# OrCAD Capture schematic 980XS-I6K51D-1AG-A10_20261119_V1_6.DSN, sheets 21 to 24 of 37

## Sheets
21 T01.GROUP1.U2: size D
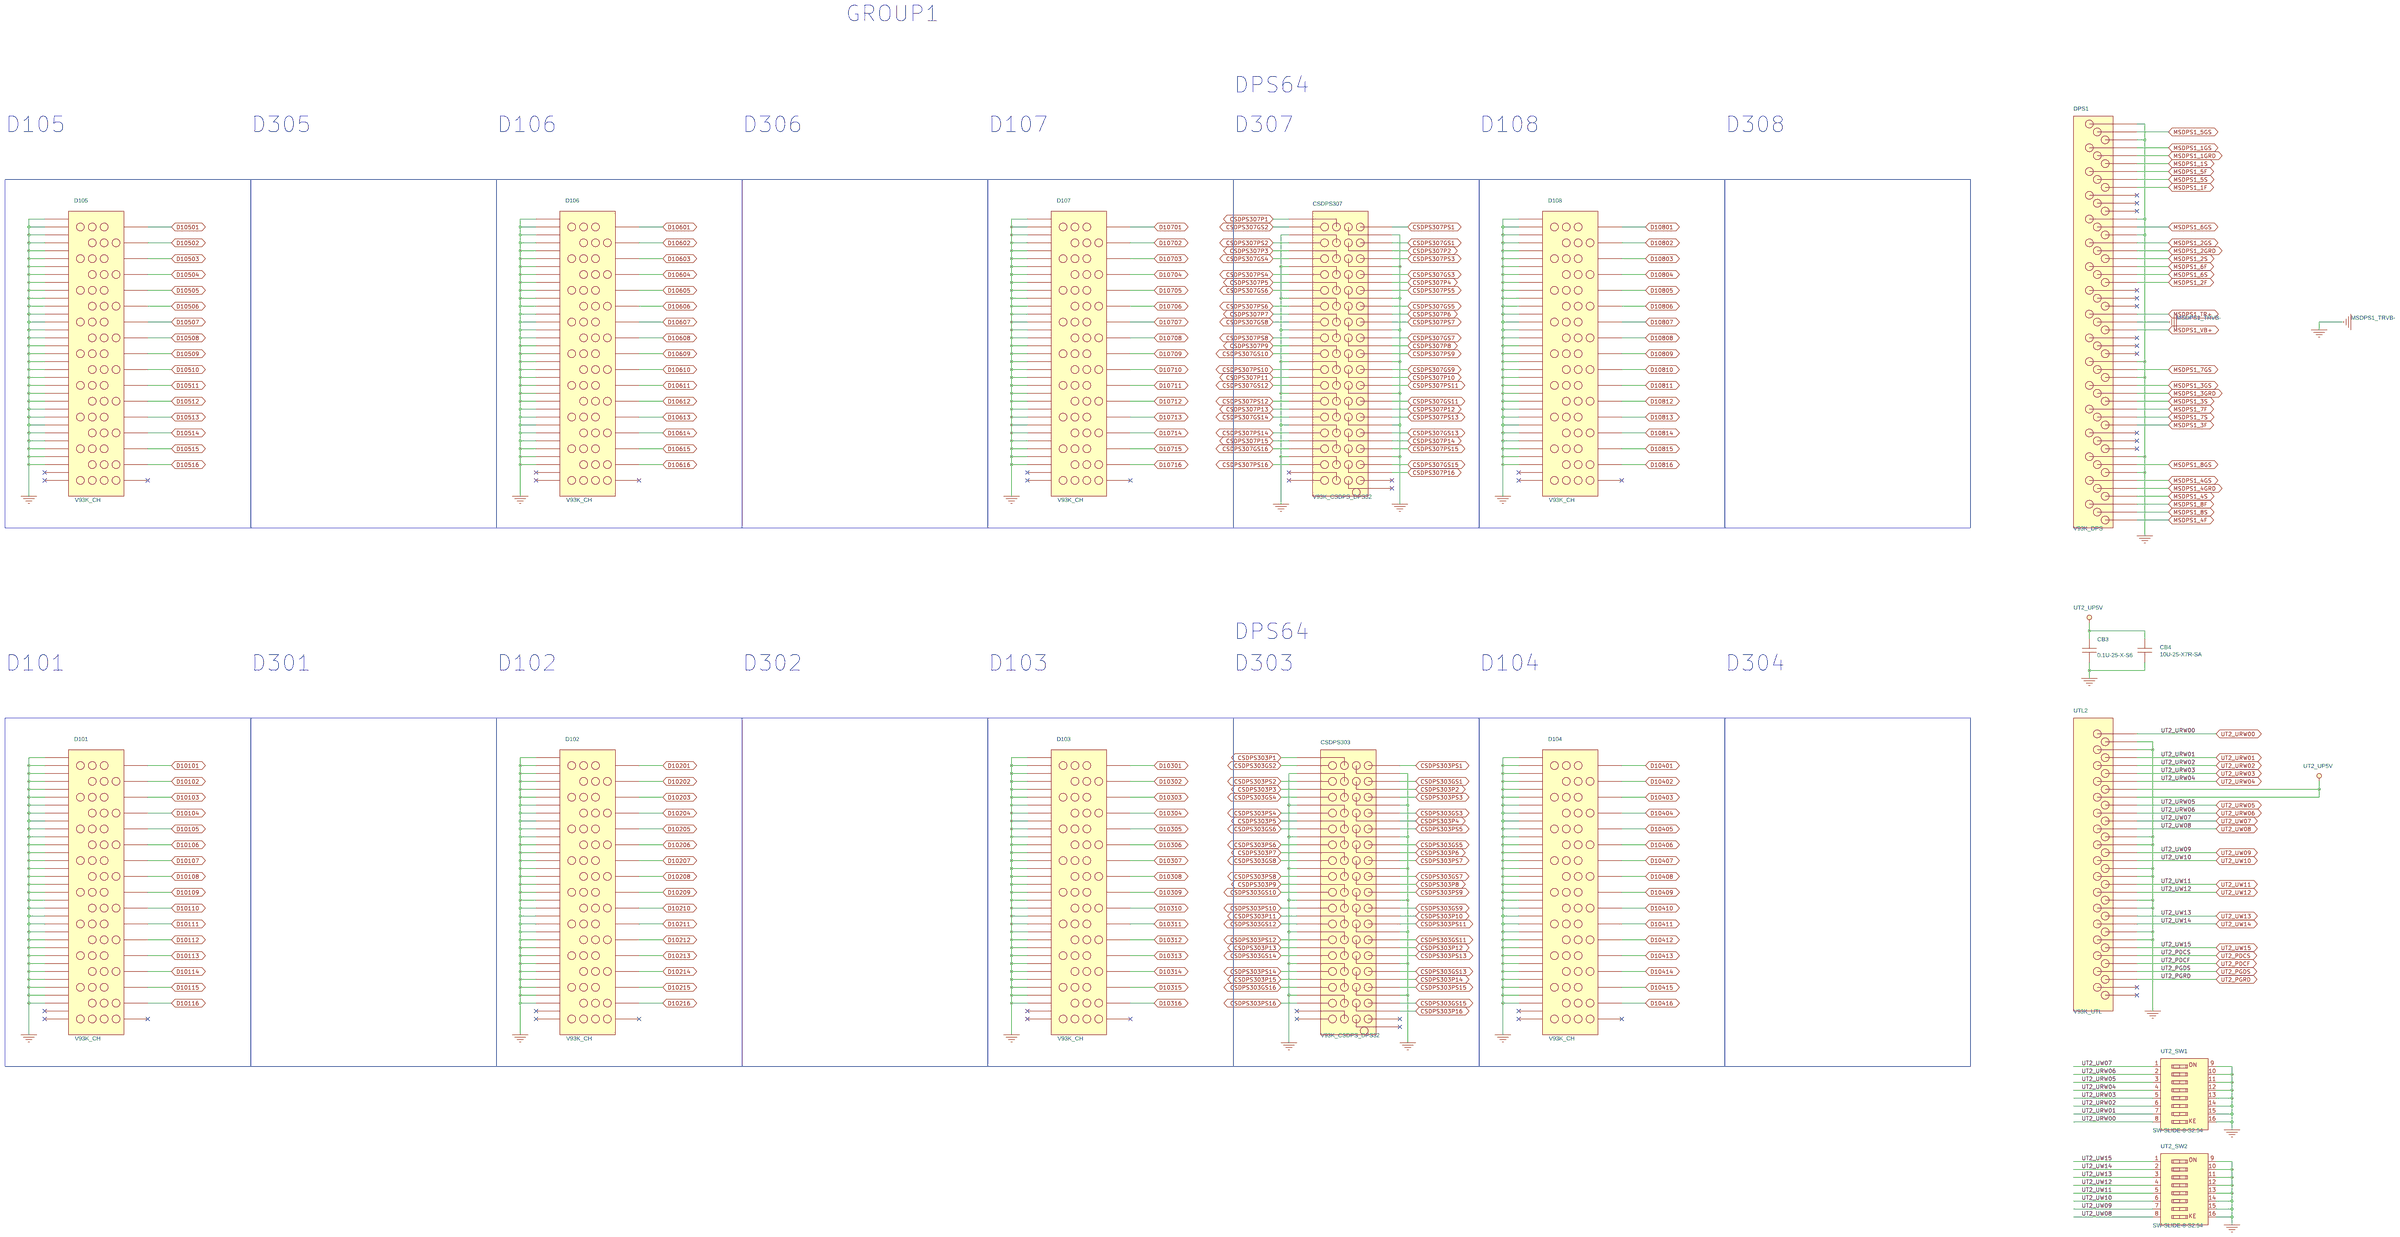
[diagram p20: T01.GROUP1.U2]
22 T02.GROUP2.U3: size D
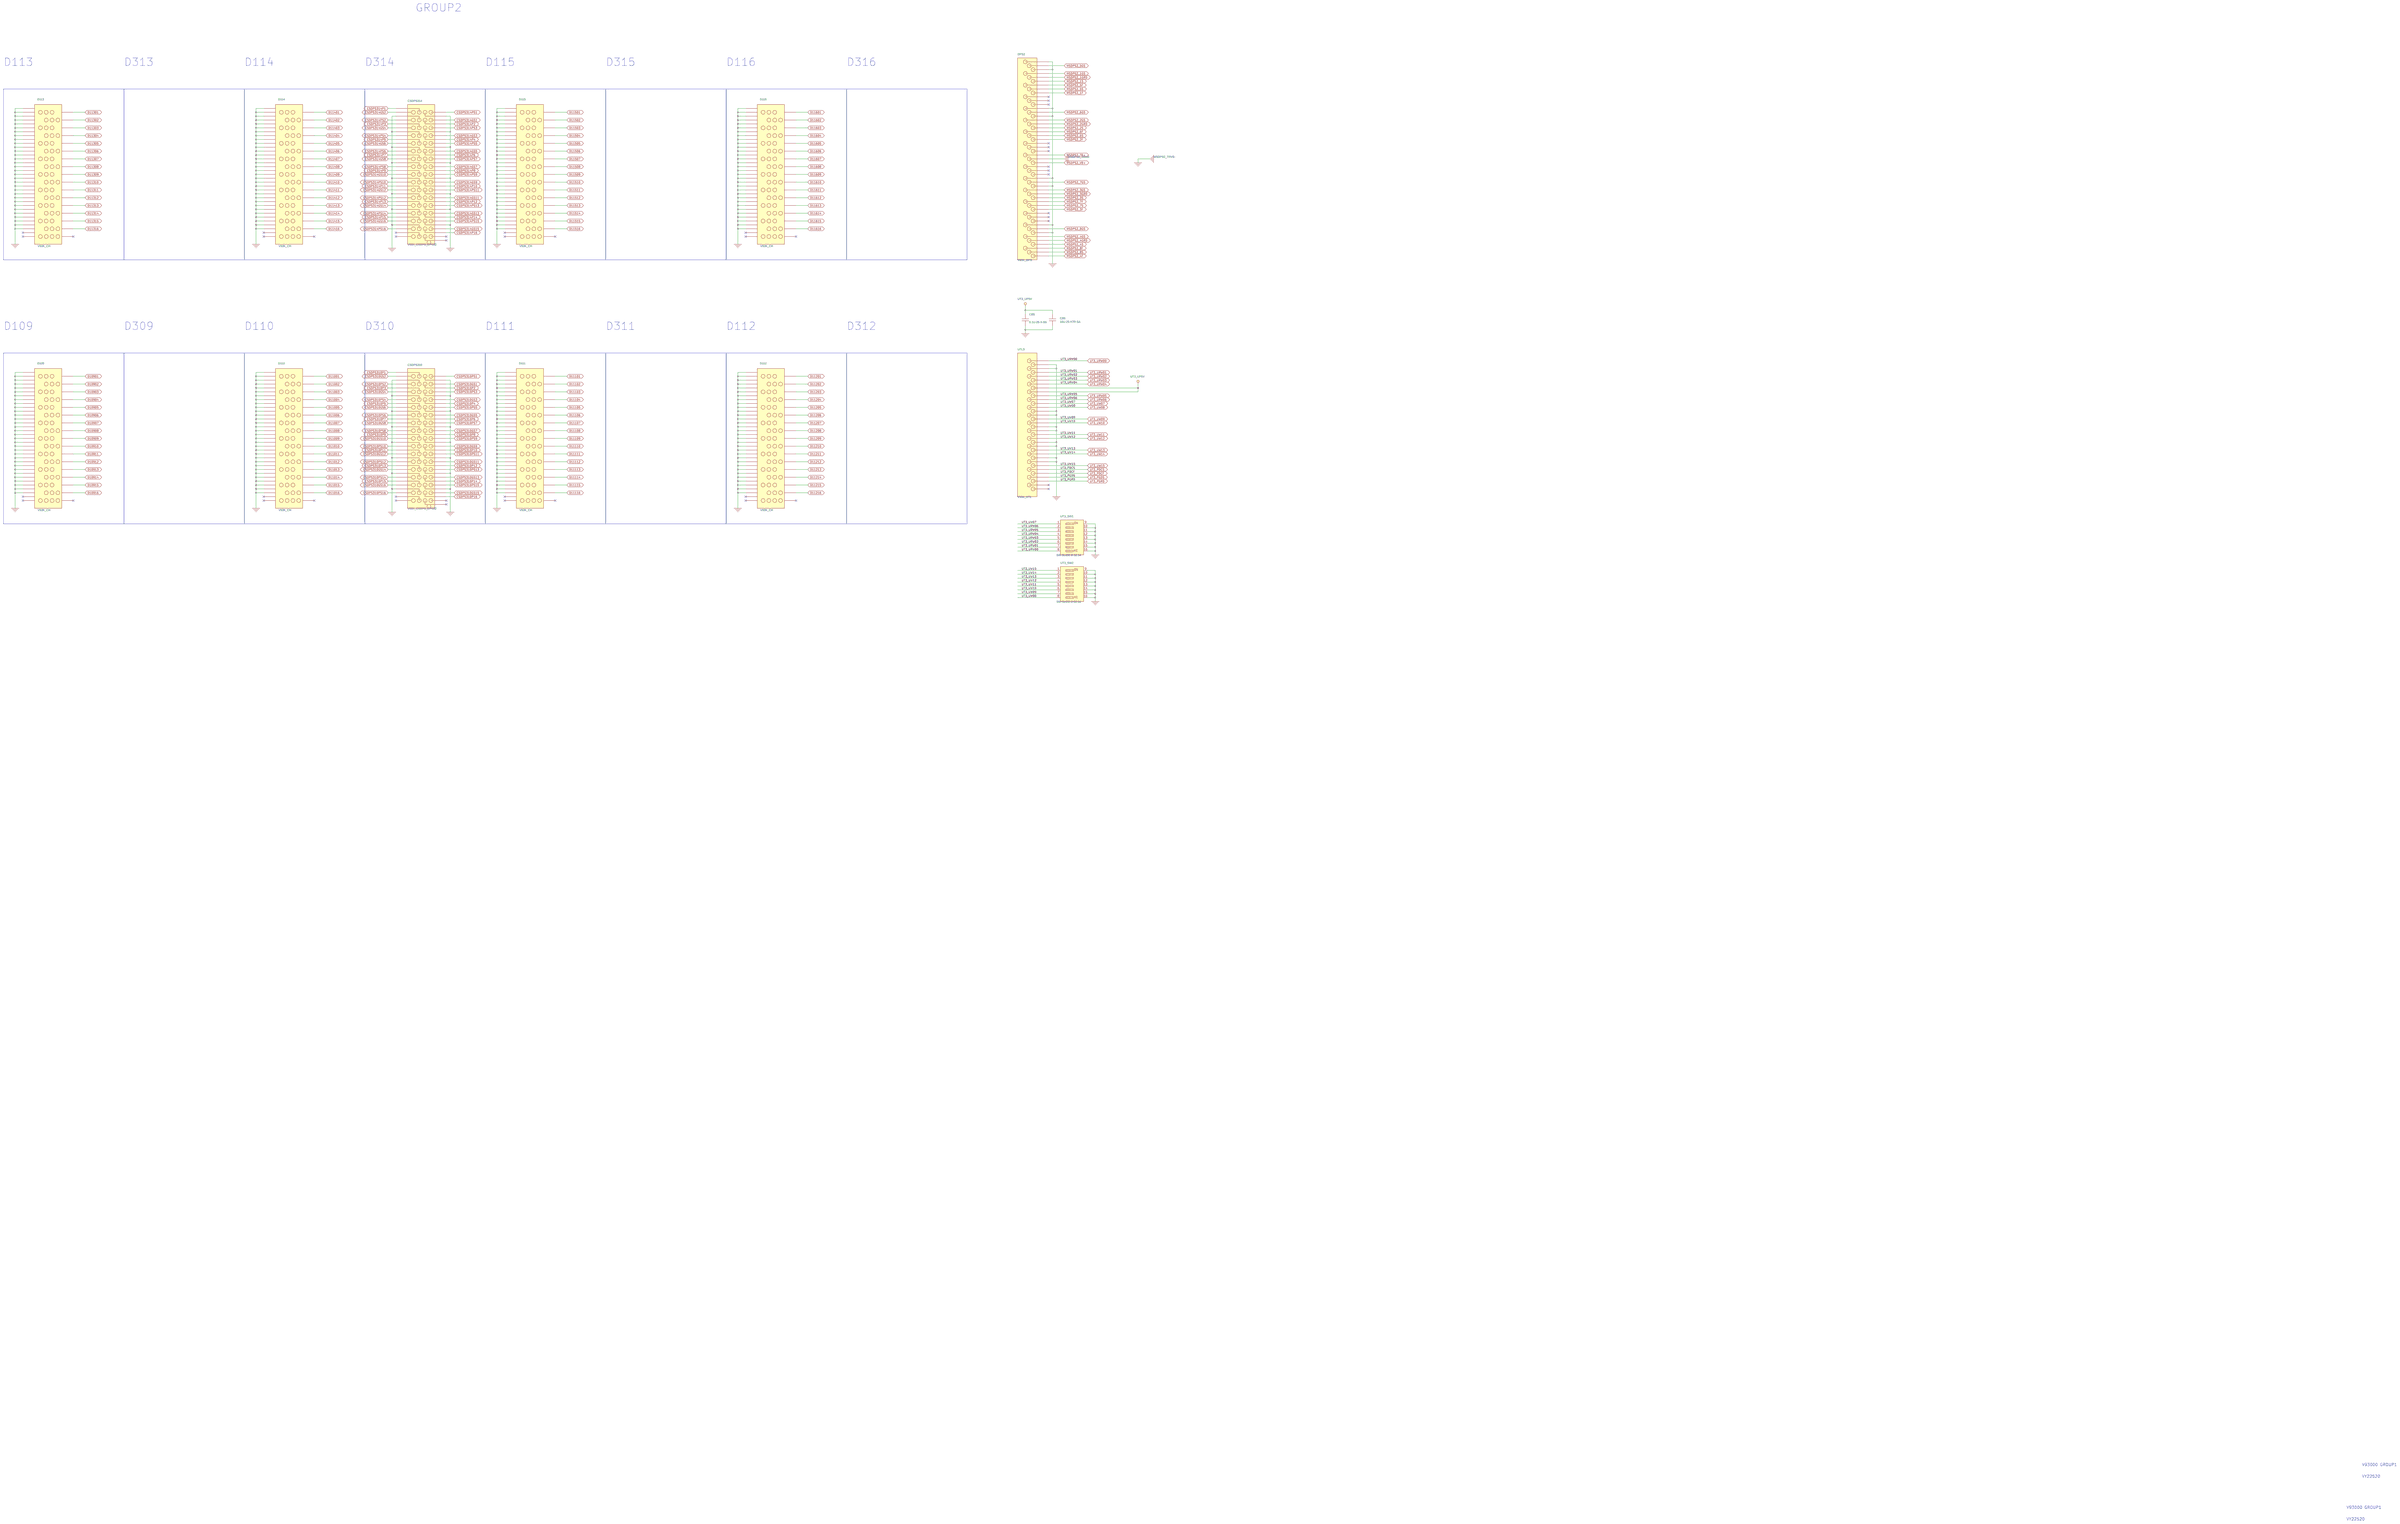
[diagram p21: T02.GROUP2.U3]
23 T03.GROUP3.U1: size D
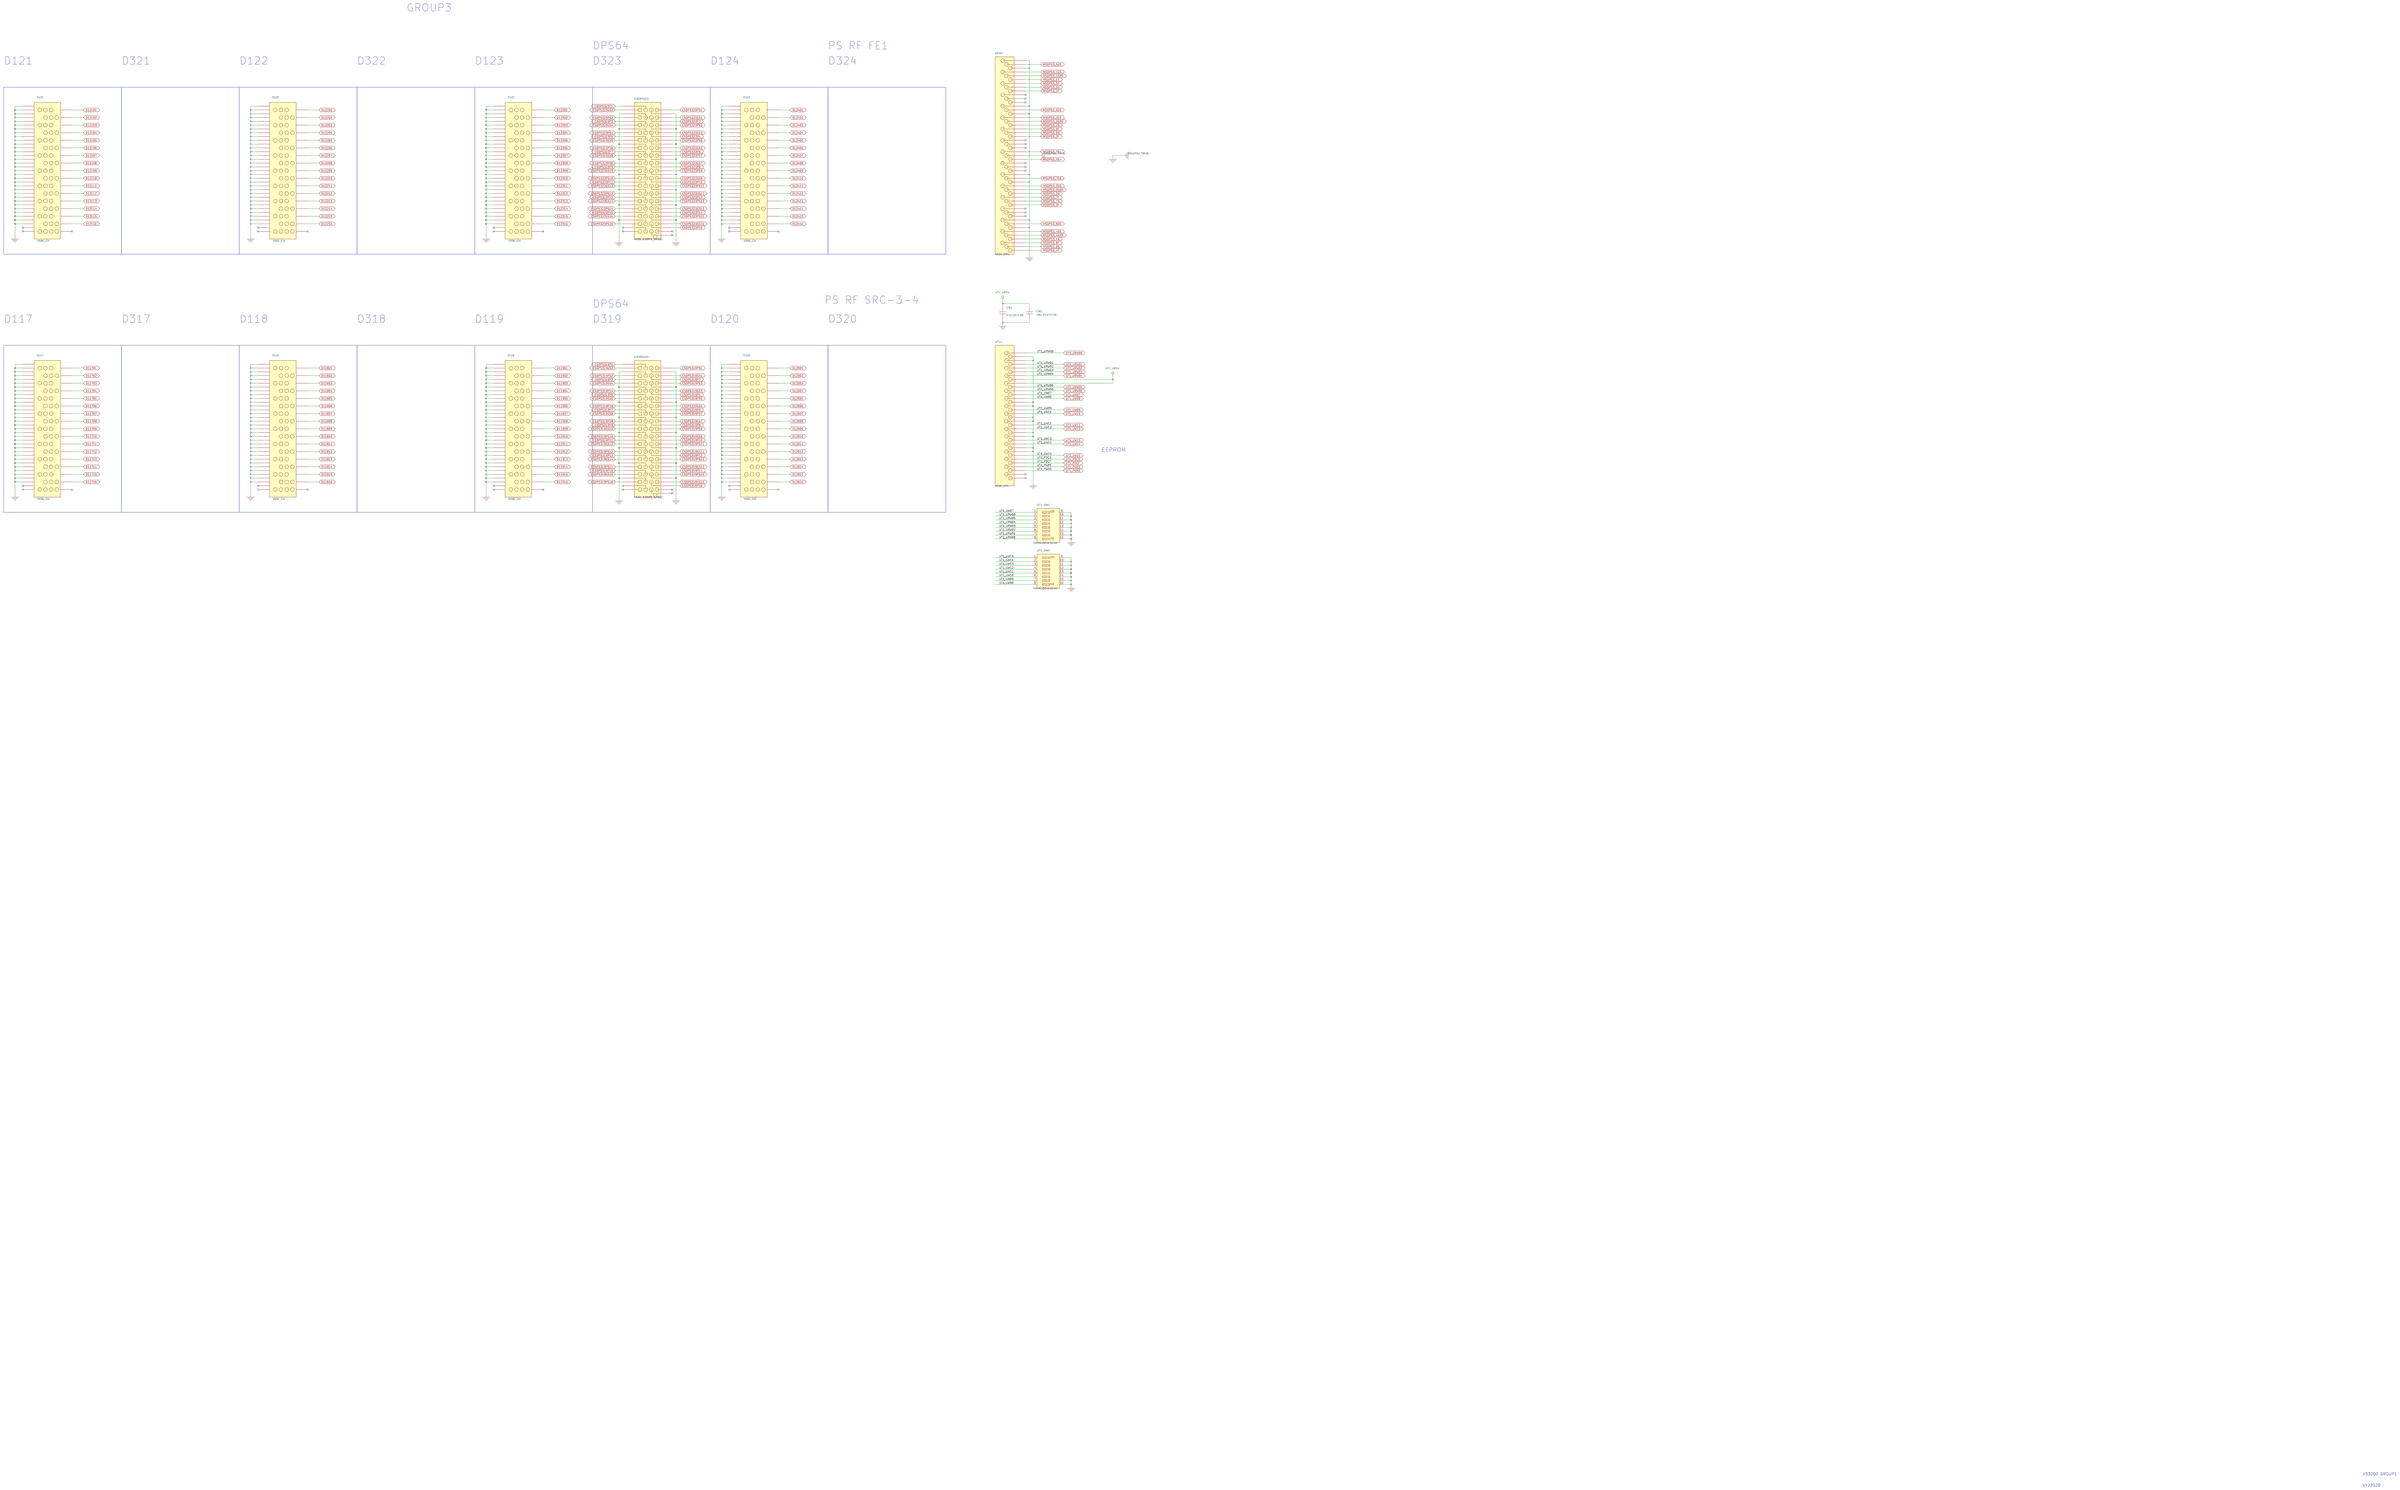
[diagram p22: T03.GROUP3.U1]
24 T04.GROUP8.U4: size D
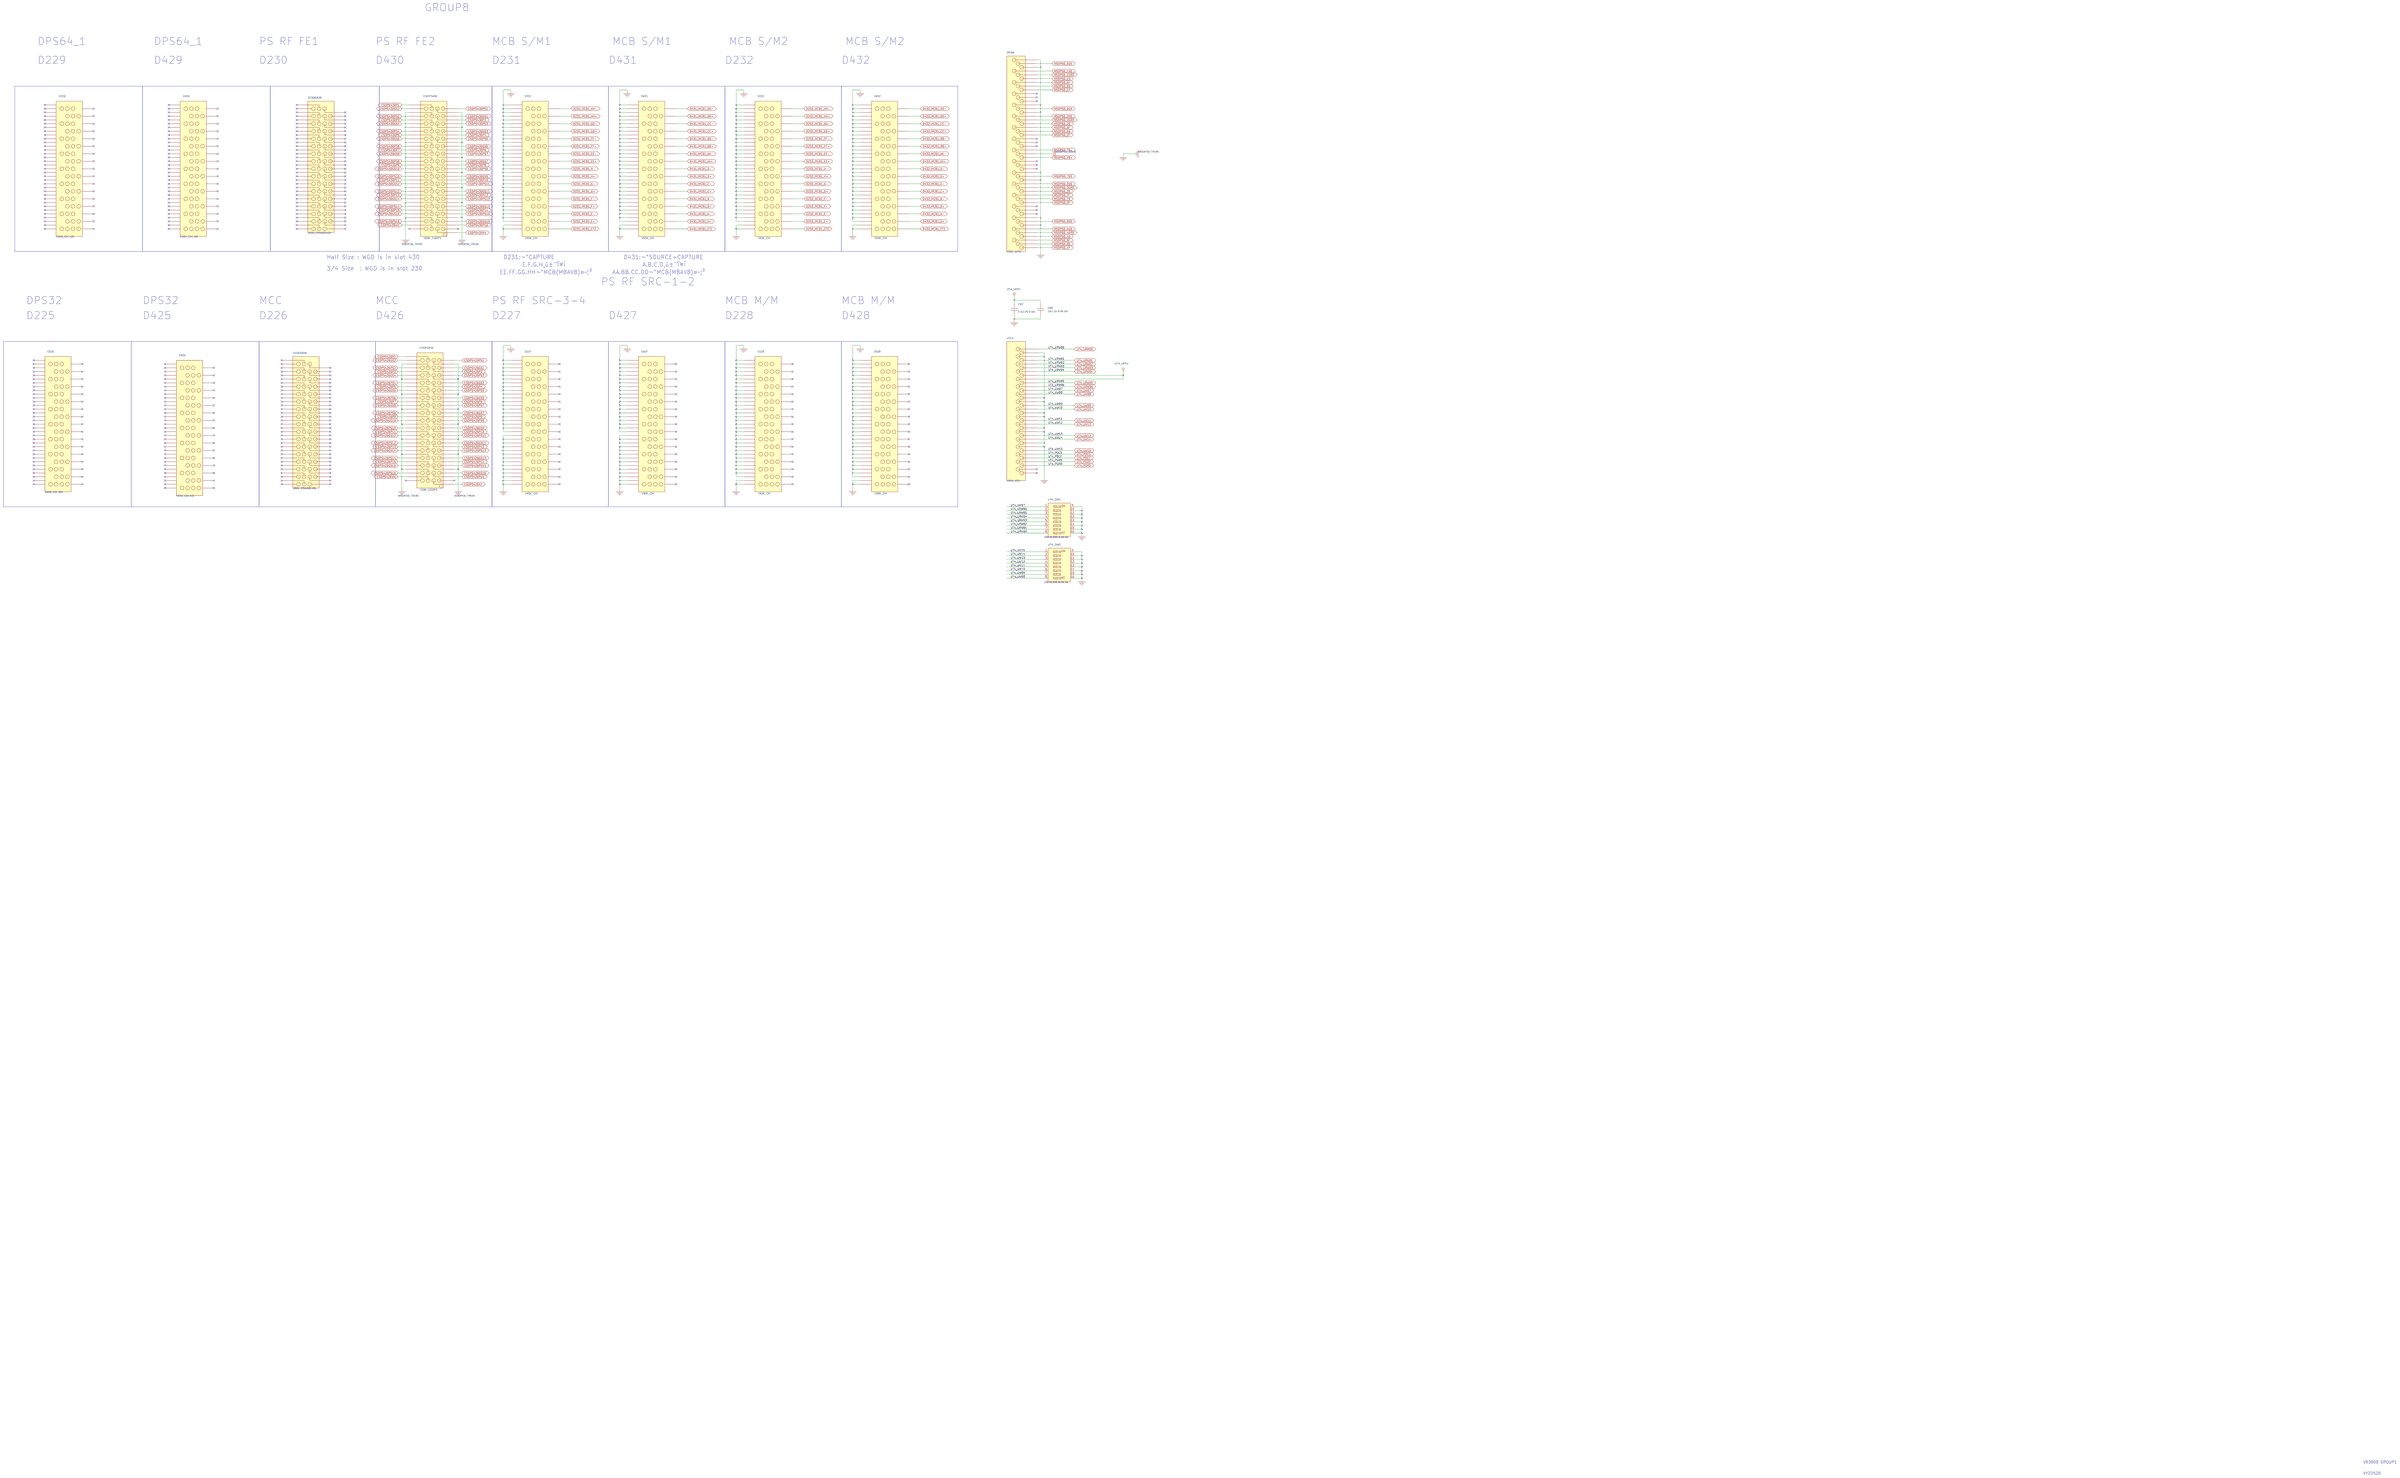
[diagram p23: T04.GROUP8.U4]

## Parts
sheet T01.GROUP1.U2
CB3  0.1U-25-X-S6  [C0603]
CB4  10U-25-X7R-SA  [C1206]
CSDPS303  V93K_CSDPS_DPS32  [PG_VG93K_PF_DPS32_G1D303]
CSDPS307  V93K_CSDPS_DPS32  [PG_VG93K_PF_DPS32_G1D307]
D101  V93K_CH  [PG_VG93K_F_G1D101]
D102  V93K_CH  [PG_VG93K_F_G1D102]
D103  V93K_CH  [PG_VG93K_F_G1D103]
D104  V93K_CH  [PG_VG93K_F_G1D104]
D105  V93K_CH  [PG_VG93K_F_G1D105]
D106  V93K_CH  [PG_VG93K_F_G1D106]
D107  V93K_CH  [PG_VG93K_F_G1D107]
D108  V93K_CH  [PG_VG93K_F_G1D108]
DPS1  V93K_DPS  [PG_VG93K_F_G1DPS1]
UT2_SW1  SW-SLIDE-8-S2.54  [SW8X2_2P54MM_16P_SMD]
UT2_SW2  SW-SLIDE-8-S2.54  [SW8X2_2P54MM_16P_SMD]
UTL2  V93K_UTL  [PG_VG93K_F_G1UTI2]
sheet T02.GROUP2.U3
CB5  0.1U-25-X-S6  [C0603]
CB6  10U-25-X7R-SA  [C1206]
CSDPS310  V93K_CSDPS_DPS32  [PG_VG93K_PF_DPS32_G2D310]
CSDPS314  V93K_CSDPS_DPS32  [PG_VG93K_PF_DPS32_G2D314]
D109  V93K_CH  [PG_VG93K_F_G2D109]
D110  V93K_CH  [PG_VG93K_F_G2D110]
D111  V93K_CH  [PG_VG93K_F_G2D111]
D112  V93K_CH  [PG_VG93K_F_G2D112]
D113  V93K_CH  [PG_VG93K_F_G2D113]
D114  V93K_CH  [PG_VG93K_F_G2D114]
D115  V93K_CH  [PG_VG93K_F_G2D115]
D116  V93K_CH  [PG_VG93K_F_G2D116]
DPS2  V93K_DPS  [PG_VG93K_F_G2DPS2]
UT3_SW1  SW-SLIDE-8-S2.54  [SW8X2_2P54MM_16P_SMD]
UT3_SW2  SW-SLIDE-8-S2.54  [SW8X2_2P54MM_16P_SMD]
UTL3  V93K_UTL  [PG_VG93K_F_G2UTI3]
sheet T03.GROUP3.U1
CB1  0.1U-25-X-S6  [C0603]
CB2  10U-25-X7R-SA  [C1206]
CSDPS319  V93K_CSDPS_DPS32  [PG_VG93K_PF_DPS32_G3D319]
CSDPS323  V93K_CSDPS_DPS32  [PG_VG93K_PF_DPS32_G3D323]
D117  V93K_CH  [PG_VG93K_F_G3D117]
D118  V93K_CH  [PG_VG93K_F_G3D118]
D119  V93K_CH  [PG_VG93K_F_G3D119]
D120  V93K_CH  [PG_VG93K_F_G3D120]
D121  V93K_CH  [PG_VG93K_F_G3D121]
D122  V93K_CH  [PG_VG93K_F_G3D122]
D123  V93K_CH  [PG_VG93K_F_G3D123]
D124  V93K_CH  [PG_VG93K_F_G3D124]
DPS3  V93K_DPS  [PG_VG93K_F_G3DPS3]
UT1_SW1  SW-SLIDE-8-S2.54  [SW8X2_2P54MM_16P_SMD]
UT1_SW2  SW-SLIDE-8-S2.54  [SW8X2_2P54MM_16P_SMD]
UTL1  V93K_UTL  [PG_VG93K_F_G3UTI1]
sheet T04.GROUP8.U4
CB7  0.1U-25-X-S6  [C0603]
CB8  10U-25-X7R-SA  [C1206]
CSDPS426  V93K_CSDPS  [PG_VG93K_PF_DPS32_G8D426]
CSDPS430  V93K_CSDPS  [PG_VG93K_PF_DPS32_G8D430]
D225  V93K_CH_ND  [PG_VG93K_F_G8D225_ND]
D226/D626  V93K_PS1600 HD  [PG_VG93K_F_HSM_G8D226_626_ND]
D227  V93K_CH  [PG_VG93K_F_G8D227]
D228  V93K_CH  [PG_VG93K_F_G8D228]
D229  V93K_CH_ND  [PG_VG93K_F_G8D229_ND]
D230/D630  V93K_PS1600 HD  [PG_VG93K_F_HSM_G8D230_630_ND]
D231  V93K_CH  [PG_VG93K_F_G8D231]
D232  V93K_CH  [PG_VG93K_F_G8D232]
D425  V93K_CH_ND  [PG_VG93K_F_G8D425_ND]
D427  V93K_CH  [PG_VG93K_F_G8D427]
D428  V93K_CH  [PG_VG93K_F_G8D428]
D429  V93K_CH_ND  [PG_VG93K_F_G8D429_ND]
D431  V93K_CH  [PG_VG93K_F_G8D431]
D432  V93K_CH  [PG_VG93K_F_G8D432]
DPS8  V93K_DPS  [PG_VG93K_F_G8DPS8]
UT4_SW1  SW-SLIDE-8-S2.54  [SW8X2_2P54MM_16P_SMD]
UT4_SW2  SW-SLIDE-8-S2.54  [SW8X2_2P54MM_16P_SMD]
UTL4  V93K_UTL  [PG_VG93K_F_G8UTI4]

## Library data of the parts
CB1 CB3 CB5 CB7 = 0.1U-25-X-S6
CB2 CB4 CB6 CB8 = 10U-25-X7R-SA
CSDPS303 CSDPS307 CSDPS310 CSDPS314 CSDPS319 CSDPS323 = V93K_CSDPS_DPS32
D101-D124 D225 D227-D229 D231 D232 D425 D427-D429 D431 D432 = V93K_CH
DPS1-DPS3 DPS8 = V93K_DPS
UT1_SW1 UT1_SW2 UT2_SW1 UT2_SW2 UT3_SW1 UT3_SW2 UT4_SW1 UT4_SW2 = SW-SLIDE-8-S2.54
UTL1-UTL4 = V93K_UTL
CSDPS426 CSDPS430 = V93K_CSDPS_A
D226/D626 D230/D630 = V93K_PS1600_HD

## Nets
DGND: CSDPS303.B2 CSDPS303.B4 CSDPS303.B6 CSDPS303.B8 CSDPS303.B10 CSDPS303.B12 CSDPS303.B14 CSDPS303.B16 CSDPS303.C1 CSDPS303.C3 CSDPS303.C5 CSDPS303.C7 CSDPS303.C9 CSDPS303.C11 CSDPS303.C13 CSDPS303.C15 CSDPS307.B2 CSDPS307.B4 CSDPS307.B6 CSDPS307.B8 CSDPS307.B10 CSDPS307.B12 CSDPS307.B14 CSDPS307.B16 CSDPS307.C1 CSDPS307.C3 CSDPS307.C5 CSDPS307.C7 CSDPS307.C9 CSDPS307.C11 CSDPS307.C13 CSDPS307.C15 CSDPS310.B2 CSDPS310.B4 CSDPS310.B6 CSDPS310.B8 CSDPS310.B10 CSDPS310.B12 CSDPS310.B14 CSDPS310.B16 CSDPS310.C1 CSDPS310.C3 CSDPS310.C5 CSDPS310.C7 CSDPS310.C9 CSDPS310.C11 CSDPS310.C13 CSDPS310.C15 CSDPS314.B2 CSDPS314.B4 CSDPS314.B6 CSDPS314.B8 CSDPS314.B10 CSDPS314.B12 CSDPS314.B14 CSDPS314.B16 CSDPS314.C1 CSDPS314.C3 CSDPS314.C5 CSDPS314.C7 CSDPS314.C9 CSDPS314.C11 CSDPS314.C13 CSDPS314.C15 CSDPS319.B2 CSDPS319.B4 CSDPS319.B6 CSDPS319.B8 CSDPS319.B10 CSDPS319.B12 CSDPS319.B14 CSDPS319.B16 CSDPS319.C1 CSDPS319.C3 CSDPS319.C5 CSDPS319.C7 CSDPS319.C9 CSDPS319.C11 CSDPS319.C13 CSDPS319.C15 CSDPS323.B2 CSDPS323.B4 CSDPS323.B6 CSDPS323.B8 CSDPS323.B10 CSDPS323.B12 CSDPS323.B14 CSDPS323.B16 CSDPS323.C1 CSDPS323.C3 CSDPS323.C5 CSDPS323.C7 CSDPS323.C9 CSDPS323.C11 CSDPS323.C13 CSDPS323.C15 CSDPS426.B2 CSDPS426.B4 CSDPS426.B6 CSDPS426.B8 CSDPS426.B10 CSDPS426.B12 CSDPS426.B14 CSDPS426.B16 CSDPS426.C1 CSDPS426.C3 CSDPS426.C5 CSDPS426.C7 CSDPS426.C9 CSDPS426.C11 CSDPS426.C13 CSDPS426.C15 CSDPS430.B2 CSDPS430.B4 CSDPS430.B6 CSDPS430.B8 CSDPS430.B10 CSDPS430.B12 CSDPS430.B14 CSDPS430.B16 CSDPS430.C1 CSDPS430.C3 CSDPS430.C5 CSDPS430.C7 CSDPS430.C9 CSDPS430.C11 CSDPS430.C13 CSDPS430.C15 D101.A1 D101.A2 D101.A3 D101.A4 D101.A5 D101.A6 D101.A7 D101.A8 D101.A9 D101.A10 D101.A11 D101.A12 D101.A13 D101.A14 D101.A15 D101.A16 D101.B1 D101.B2 D101.B3 D101.B4 D101.B5 D101.B6 D101.B7 D101.B8 D101.B9 D101.B10 D101.B11 D101.B12 D101.B13 D101.B14 D101.B15 D101.B16 D102.A1 D102.A2 D102.A3 D102.A4 D102.A5 D102.A6 D102.A7 D102.A8 D102.A9 D102.A10 D102.A11 D102.A12 D102.A13 D102.A14 D102.A15 D102.A16 D102.B1 D102.B2 D102.B3 D102.B4 D102.B5 D102.B6 D102.B7 D102.B8 D102.B9 D102.B10 D102.B11 D102.B12 D102.B13 D102.B14 D102.B15 D102.B16 D103.A1 D103.A2 D103.A3 D103.A4 D103.A5 D103.A6 D103.A7 D103.A8 D103.A9 D103.A10 D103.A11 D103.A12 D103.A13 D103.A14 D103.A15 D103.A16 D103.B1 D103.B2 D103.B3 D103.B4 D103.B5 D103.B6 D103.B7 D103.B8 D103.B9 D103.B10 D103.B11 D103.B12 D103.B13 D103.B14 D103.B15 D103.B16 D104.A1 D104.A2 D104.A3 D104.A4 D104.A5 D104.A6 D104.A7 D104.A8 D104.A9 D104.A10 D104.A11 D104.A12 D104.A13 D104.A14 D104.A15 D104.A16 D104.B1 D104.B2 D104.B3 D104.B4 D104.B5 D104.B6 D104.B7 D104.B8 D104.B9 D104.B10 D104.B11 D104.B12 D104.B13 D104.B14 D104.B15 D104.B16 D105.A1 D105.A2 D105.A3 D105.A4 D105.A5 D105.A6 D105.A7 D105.A8 D105.A9 D105.A10 D105.A11 D105.A12 D105.A13 D105.A14 D105.A15 D105.A16 D105.B1 D105.B2 D105.B3 D105.B4 D105.B5 D105.B6 D105.B7 D105.B8 D105.B9 D105.B10 D105.B11 D105.B12 D105.B13 D105.B14 D105.B15 D105.B16 D106.A1 D106.A2 D106.A3 D106.A4 D106.A5 D106.A6 D106.A7 D106.A8 D106.A9 D106.A10 D106.A11 D106.A12 D106.A13 D106.A14 D106.A15 D106.A16 D106.B1 D106.B2 D106.B3 D106.B4 D106.B5 D106.B6 D106.B7 D106.B8 D106.B9 D106.B10 D106.B11 D106.B12 D106.B13 D106.B14 D106.B15 D106.B16 D107.A1 D107.A2 D107.A3 D107.A4 D107.A5 D107.A6 D107.A7 D107.A8 D107.A9 D107.A10 D107.A11 D107.A12 D107.A13 D107.A14 D107.A15 D107.A16 D107.B1 D107.B2 D107.B3 D107.B4 D107.B5 D107.B6 D107.B7 D107.B8 D107.B9 D107.B10 D107.B11 D107.B12 D107.B13 D107.B14 D107.B15 D107.B16 D108.A1 D108.A2 D108.A3 D108.A4 D108.A5 D108.A6 D108.A7 D108.A8 D108.A9 D108.A10 D108.A11 D108.A12 D108.A13 D108.A14 D108.A15 D108.A16 D108.B1 D108.B2 D108.B3 D108.B4 D108.B5 D108.B6 D108.B7 D108.B8 D108.B9 D108.B10 D108.B11 D108.B12 D108.B13 D108.B14 D108.B15 D108.B16 D109.A1 D109.A2 D109.A3 D109.A4 D109.A5 D109.A6 D109.A7 D109.A8 D109.A9 D109.A10 D109.A11 D109.A12 D109.A13 D109.A14 D109.A15 D109.A16 D109.B1 D109.B2 D109.B3 D109.B4 D109.B5 D109.B6 D109.B7 D109.B8 D109.B9 D109.B10 D109.B11 D109.B12 D109.B13 D109.B14 D109.B15 D109.B16 D110.A1 D110.A2 D110.A3 D110.A4 D110.A5 D110.A6 D110.A7 D110.A8 D110.A9 D110.A10 D110.A11 D110.A12 D110.A13 D110.A14 D110.A15 D110.A16 D110.B1 D110.B2 D110.B3 D110.B4 D110.B5 D110.B6 D110.B7 D110.B8 D110.B9 D110.B10 D110.B11 D110.B12 D110.B13 D110.B14 D110.B15 D110.B16 D111.A1 D111.A2 D111.A3 D111.A4 D111.A5 D111.A6 D111.A7 D111.A8 D111.A9 D111.A10 D111.A11 D111.A12 D111.A13 D111.A14 D111.A15 D111.A16 D111.B1 D111.B2 D111.B3 D111.B4 D111.B5 D111.B6 D111.B7 D111.B8 D111.B9 D111.B10 D111.B11 D111.B12 D111.B13 D111.B14 D111.B15 D111.B16 D112.A1 D112.A2 D112.A3 D112.A4 D112.A5 D112.A6 D112.A7 D112.A8 D112.A9 D112.A10 D112.A11 D112.A12 D112.A13 D112.A14 D112.A15 D112.A16 D112.B1 D112.B2 D112.B3 D112.B4 D112.B5 D112.B6 D112.B7 D112.B8 D112.B9 D112.B10 D112.B11 D112.B12 D112.B13 D112.B14 D112.B15 D112.B16 D113.A1 D113.A2 D113.A3 D113.A4 D113.A5 D113.A6 D113.A7 D113.A8 D113.A9 D113.A10 D113.A11 D113.A12 D113.A13 D113.A14 D113.A15 D113.A16 D113.B1 D113.B2 D113.B3 D113.B4 D113.B5 D113.B6 D113.B7 D113.B8 D113.B9 D113.B10 D113.B11 D113.B12 D113.B13 D113.B14 D113.B15 D113.B16 D114.A1 D114.A2 D114.A3 D114.A4 D114.A5 D114.A6 D114.A7 D114.A8 D114.A9 D114.A10 D114.A11 D114.A12 D114.A13 D114.A14 D114.A15 D114.A16 D114.B1 D114.B2 D114.B3 D114.B4 D114.B5 D114.B6 D114.B7 D114.B8 D114.B9 D114.B10 D114.B11 D114.B12 D114.B13 D114.B14 D114.B15 D114.B16 D115.A1 D115.A2 D115.A3 D115.A4 D115.A5 D115.A6 D115.A7 D115.A8 D115.A9 D115.A10 D115.A11 D115.A12 D115.A13 D115.A14 D115.A15 D115.A16 D115.B1 D115.B2 D115.B3 D115.B4 D115.B5 D115.B6 D115.B7 D115.B8 D115.B9 D115.B10 D115.B11 D115.B12 D115.B13 D115.B14 D115.B15 D115.B16 D116.A1 D116.A2 D116.A3 D116.A4 D116.A5 D116.A6 D116.A7 D116.A8 D116.A9 D116.A10 D116.A11 D116.A12 D116.A13 D116.A14 D116.A15 D116.A16 D116.B1 D116.B2 D116.B3 D116.B4 D116.B5 D116.B6 D116.B7 D116.B8 D116.B9 D116.B10 D116.B11 D116.B12 D116.B13 D116.B14 D116.B15 D116.B16 D117.A1 D117.A2 D117.A3 D117.A4 D117.A5 D117.A6 D117.A7 D117.A8 D117.A9 D117.A10 D117.A11 D117.A12 D117.A13 D117.A14 D117.A15 D117.A16 D117.B1 D117.B2 D117.B3 D117.B4 D117.B5 D117.B6 D117.B7 D117.B8 D117.B9 D117.B10 D117.B11 D117.B12 D117.B13 D117.B14 D117.B15 D117.B16 D118.A1 D118.A2 D118.A3 D118.A4 D118.A5 D118.A6 D118.A7 D118.A8 D118.A9 D118.A10 D118.A11 D118.A12 D118.A13 D118.A14 D118.A15 D118.A16 D118.B1 D118.B2 D118.B3 D118.B4 D118.B5 D118.B6 D118.B7 D118.B8 D118.B9 D118.B10 D118.B11 D118.B12 D118.B13 D118.B14 D118.B15 D118.B16 D119.A1 D119.A2 D119.A3 D119.A4 D119.A5 D119.A6 D119.A7 D119.A8 D119.A9 D119.A10 D119.A11 D119.A12 D119.A13 D119.A14 D119.A15 D119.A16 D119.B1 D119.B2 D119.B3 D119.B4 D119.B5 D119.B6 D119.B7 D119.B8 D119.B9 D119.B10 D119.B11 D119.B12 D119.B13 D119.B14 D119.B15 D119.B16 D120.A1 D120.A2 D120.A3 D120.A4 D120.A5 D120.A6 D120.A7 D120.A8 D120.A9 D120.A10 D120.A11 D120.A12 D120.A13 D120.A14 D120.A15 D120.A16 D120.B1 D120.B2 D120.B3 D120.B4 D120.B5 D120.B6 D120.B7 D120.B8 D120.B9 D120.B10 D120.B11 D120.B12 D120.B13 D120.B14 D120.B15 D120.B16 D121.A1 D121.A2 D121.A3 D121.A4 D121.A5 D121.A6 D121.A7 D121.A8 D121.A9 D121.A10 D121.A11 D121.A12 D121.A13 D121.A14 D121.A15 D121.A16 D121.B1 D121.B2 D121.B3 D121.B4 D121.B5 D121.B6 D121.B7 D121.B8 D121.B9 D121.B10 D121.B11 D121.B12 D121.B13 D121.B14 D121.B15 D121.B16 D122.A1 D122.A2 D122.A3 D122.A4 D122.A5 D122.A6 D122.A7 D122.A8 D122.A9 D122.A10 D122.A11 D122.A12 D122.A13 D122.A14 D122.A15 D122.A16 D122.B1 D122.B2 D122.B3 D122.B4 D122.B5 D122.B6 D122.B7 D122.B8 D122.B9 D122.B10 D122.B11 D122.B12 D122.B13 D122.B14 D122.B15 D122.B16 D123.A1 D123.A2 D123.A3 D123.A4 D123.A5 D123.A6 D123.A7 D123.A8 D123.A9 D123.A10 D123.A11 D123.A12 D123.A13 D123.A14 D123.A15 D123.A16 D123.B1 D123.B2 D123.B3 D123.B4 D123.B5 D123.B6 D123.B7 D123.B8 D123.B9 D123.B10 D123.B11 D123.B12 D123.B13 D123.B14 D123.B15 D123.B16 D124.A1 D124.A2 D124.A3 D124.A4 D124.A5 D124.A6 D124.A7 D124.A8 D124.A9 D124.A10 D124.A11 D124.A12 D124.A13 D124.A14 D124.A15 D124.A16 D124.B1 D124.B2 D124.B3 D124.B4 D124.B5 D124.B6 D124.B7 D124.B8 D124.B9 D124.B10 D124.B11 D124.B12 D124.B13 D124.B14 D124.B15 D124.B16 D227.A1 D227.A2 D227.A3 D227.A4 D227.A5 D227.A6 D227.A7 D227.A8 D227.A9 D227.A10 D227.A11 D227.A12 D227.A13 D227.A14 D227.A15 D227.A16 D227.A17 D227.B1 D227.B2 D227.B3 D227.B4 D227.B5 D227.B6 D227.B7 D227.B8 D227.B9 D227.B10 D227.B11 D227.B12 D227.B13 D227.B14 D227.B15 D227.B16 D227.B17 D228.A1 D228.A2 D228.A3 D228.A4 D228.A5 D228.A6 D228.A7 D228.A8 D228.A9 D228.A10 D228.A11 D228.A12 D228.A13 D228.A14 D228.A15 D228.A16 D228.A17 D228.B1 D228.B2 D228.B3 D228.B4 D228.B5 D228.B6 D228.B7 D228.B8 D228.B9 D228.B10 D228.B11 D228.B12 D228.B13 D228.B14 D228.B15 D228.B16 D228.B17 D231.A1 D231.A2 D231.A3 D231.A4 D231.A5 D231.A6 D231.A7 D231.A8 D231.A9 D231.A10 D231.A11 D231.A12 D231.A13 D231.A14 D231.A15 D231.A16 D231.A17 D231.B1 D231.B2 D231.B3 D231.B4 D231.B5 D231.B6 D231.B7 D231.B8 D231.B9 D231.B10 D231.B11 D231.B12 D231.B13 D231.B14 D231.B15 D231.B16 D231.B17 D232.A1 D232.A2 D232.A3 D232.A4 D232.A5 D232.A6 D232.A7 D232.A8 D232.A9 D232.A10 D232.A11 D232.A12 D232.A13 D232.A14 D232.A15 D232.A16 D232.A17 D232.B1 D232.B2 D232.B3 D232.B4 D232.B5 D232.B6 D232.B7 D232.B8 D232.B9 D232.B10 D232.B11 D232.B12 D232.B13 D232.B14 D232.B15 D232.B16 D232.B17 D427.A1 D427.A2 D427.A3 D427.A4 D427.A5 D427.A6 D427.A7 D427.A8 D427.A9 D427.A10 D427.A11 D427.A12 D427.A13 D427.A14 D427.A15 D427.A16 D427.A17 D427.B1 D427.B2 D427.B3 D427.B4 D427.B5 D427.B6 D427.B7 D427.B8 D427.B9 D427.B10 D427.B11 D427.B12 D427.B13 D427.B14 D427.B15 D427.B16 D427.B17 D428.A1 D428.A2 D428.A3 D428.A4 D428.A5 D428.A6 D428.A7 D428.A8 D428.A9 D428.A10 D428.A11 D428.A12 D428.A13 D428.A14 D428.A15 D428.A16 D428.A17 D428.B1 D428.B2 D428.B3 D428.B4 D428.B5 D428.B6 D428.B7 D428.B8 D428.B9 D428.B10 D428.B11 D428.B12 D428.B13 D428.B14 D428.B15 D428.B16 D428.B17 D431.A1 D431.A2 D431.A3 D431.A4 D431.A5 D431.A6 D431.A7 D431.A8 D431.A9 D431.A10 D431.A11 D431.A12 D431.A13 D431.A14 D431.A15 D431.A16 D431.A17 D431.B1 D431.B2 D431.B3 D431.B4 D431.B5 D431.B6 D431.B7 D431.B8 D431.B9 D431.B10 D431.B11 D431.B12 D431.B13 D431.B14 D431.B15 D431.B16 D431.B17 D432.A1 D432.A2 D432.A3 D432.A4 D432.A5 D432.A6 D432.A7 D432.A8 D432.A9 D432.A10 D432.A11 D432.A12 D432.A13 D432.A14 D432.A15 D432.A16 D432.A17 D432.B1 D432.B2 D432.B3 D432.B4 D432.B5 D432.B6 D432.B7 D432.B8 D432.B9 D432.B10 D432.B11 D432.B12 D432.B13 D432.B14 D432.B15 D432.B16 D432.B17 DPS1.A01 DPS1.A05 DPS1.A11 DPS1.A15 DPS1.B09 DPS1.C01 DPS1.C05 DPS1.C11 DPS1.C15 DPS2.A01 DPS2.A05 DPS2.A11 DPS2.A15 DPS2.B09 DPS2.C01 DPS2.C05 DPS2.C11 DPS2.C15 DPS3.A01 DPS3.A05 DPS3.A11 DPS3.A15 DPS3.B09 DPS3.C01 DPS3.C05 DPS3.C11 DPS3.C15 DPS8.A01 DPS8.A05 DPS8.A11 DPS8.A15 DPS8.B09 DPS8.C01 DPS8.C05 DPS8.C11 DPS8.C15 UT1_SW1.9 UT1_SW1.10 UT1_SW1.11 UT1_SW1.12 UT1_SW1.13 UT1_SW1.14 UT1_SW1.15 UT1_SW1.16 UT1_SW2.9 UT1_SW2.10 UT1_SW2.11 UT1_SW2.12 UT1_SW2.13 UT1_SW2.14 UT1_SW2.15 UT1_SW2.16 UT2_SW1.9 UT2_SW1.10 UT2_SW1.11 UT2_SW1.12 UT2_SW1.13 UT2_SW1.14 UT2_SW1.15 UT2_SW1.16 UT2_SW2.9 UT2_SW2.10 UT2_SW2.11 UT2_SW2.12 UT2_SW2.13 UT2_SW2.14 UT2_SW2.15 UT2_SW2.16 UT3_SW1.9 UT3_SW1.10 UT3_SW1.11 UT3_SW1.12 UT3_SW1.13 UT3_SW1.14 UT3_SW1.15 UT3_SW1.16 UT3_SW2.9 UT3_SW2.10 UT3_SW2.11 UT3_SW2.12 UT3_SW2.13 UT3_SW2.14 UT3_SW2.15 UT3_SW2.16 UT4_SW1.9 UT4_SW1.10 UT4_SW1.11 UT4_SW1.12 UT4_SW1.13 UT4_SW1.14 UT4_SW1.15 UT4_SW1.16 UT4_SW2.9 UT4_SW2.10 UT4_SW2.11 UT4_SW2.12 UT4_SW2.13 UT4_SW2.14 UT4_SW2.15 UT4_SW2.16 ; also on sheet 1 2 3 4 5 6 7 8 9 10 11 12 13 14 17 18 19 20 25 26 27 28 30 31 32 33 34 35 36 37
CSDPS303GS1: CSDPS303.D2
CSDPS303GS2: CSDPS303.A1
CSDPS303GS3: CSDPS303.D4
CSDPS303GS4: CSDPS303.A3
CSDPS303GS5: CSDPS303.D6
CSDPS303GS6: CSDPS303.A5
CSDPS303GS7: CSDPS303.D8
CSDPS303GS8: CSDPS303.A7
CSDPS303GS9: CSDPS303.D10
CSDPS303GS10: CSDPS303.A9
CSDPS303GS11: CSDPS303.D12
CSDPS303GS12: CSDPS303.A11
CSDPS303GS13: CSDPS303.D14
CSDPS303GS14: CSDPS303.A13
CSDPS303GS15: CSDPS303.D16
CSDPS303GS16: CSDPS303.A15
CSDPS303P1: CSDPS303.B1
CSDPS303P2: CSDPS303.C2
CSDPS303P3: CSDPS303.B3
CSDPS303P4: CSDPS303.C4
CSDPS303P5: CSDPS303.B5
CSDPS303P6: CSDPS303.C6
CSDPS303P7: CSDPS303.B7
CSDPS303P8: CSDPS303.C8
CSDPS303P9: CSDPS303.B9
CSDPS303P10: CSDPS303.C10
CSDPS303P11: CSDPS303.B11
CSDPS303P12: CSDPS303.C12
CSDPS303P13: CSDPS303.B13
CSDPS303P14: CSDPS303.C14
CSDPS303P15: CSDPS303.B15
CSDPS303P16: CSDPS303.C16
CSDPS303PS1: CSDPS303.D1
CSDPS303PS2: CSDPS303.A2
CSDPS303PS3: CSDPS303.D3
CSDPS303PS4: CSDPS303.A4
CSDPS303PS5: CSDPS303.D5
CSDPS303PS6: CSDPS303.A6
CSDPS303PS7: CSDPS303.D7
CSDPS303PS8: CSDPS303.A8
CSDPS303PS9: CSDPS303.D9
CSDPS303PS10: CSDPS303.A10
CSDPS303PS11: CSDPS303.D11
CSDPS303PS12: CSDPS303.A12
CSDPS303PS13: CSDPS303.D13
CSDPS303PS14: CSDPS303.A14
CSDPS303PS15: CSDPS303.D15
CSDPS303PS16: CSDPS303.A16
CSDPS307GS1: CSDPS307.D2
CSDPS307GS2: CSDPS307.A1
CSDPS307GS3: CSDPS307.D4
CSDPS307GS4: CSDPS307.A3
CSDPS307GS5: CSDPS307.D6
CSDPS307GS6: CSDPS307.A5
CSDPS307GS7: CSDPS307.D8
CSDPS307GS8: CSDPS307.A7
CSDPS307GS9: CSDPS307.D10
CSDPS307GS10: CSDPS307.A9
CSDPS307GS11: CSDPS307.D12
CSDPS307GS12: CSDPS307.A11
CSDPS307GS13: CSDPS307.D14
CSDPS307GS14: CSDPS307.A13
CSDPS307GS15: CSDPS307.D16
CSDPS307GS16: CSDPS307.A15
CSDPS307P1: CSDPS307.B1
CSDPS307P2: CSDPS307.C2
CSDPS307P3: CSDPS307.B3
CSDPS307P4: CSDPS307.C4
CSDPS307P5: CSDPS307.B5
CSDPS307P6: CSDPS307.C6
CSDPS307P7: CSDPS307.B7
CSDPS307P8: CSDPS307.C8
CSDPS307P9: CSDPS307.B9
CSDPS307P10: CSDPS307.C10
CSDPS307P11: CSDPS307.B11
CSDPS307P12: CSDPS307.C12
CSDPS307P13: CSDPS307.B13
CSDPS307P14: CSDPS307.C14
CSDPS307P15: CSDPS307.B15
CSDPS307P16: CSDPS307.C16
CSDPS307PS1: CSDPS307.D1
CSDPS307PS2: CSDPS307.A2
CSDPS307PS3: CSDPS307.D3
CSDPS307PS4: CSDPS307.A4
CSDPS307PS5: CSDPS307.D5
CSDPS307PS6: CSDPS307.A6
CSDPS307PS7: CSDPS307.D7
CSDPS307PS8: CSDPS307.A8
CSDPS307PS9: CSDPS307.D9
CSDPS307PS10: CSDPS307.A10
CSDPS307PS11: CSDPS307.D11
CSDPS307PS12: CSDPS307.A12
CSDPS307PS13: CSDPS307.D13
CSDPS307PS14: CSDPS307.A14
CSDPS307PS15: CSDPS307.D15
CSDPS307PS16: CSDPS307.A16
CSDPS310GS1: CSDPS310.D2
CSDPS310GS2: CSDPS310.A1
CSDPS310GS3: CSDPS310.D4
CSDPS310GS4: CSDPS310.A3
CSDPS310GS5: CSDPS310.D6
CSDPS310GS6: CSDPS310.A5
CSDPS310GS7: CSDPS310.D8
CSDPS310GS8: CSDPS310.A7
CSDPS310GS9: CSDPS310.D10
CSDPS310GS10: CSDPS310.A9
CSDPS310GS11: CSDPS310.D12
CSDPS310GS12: CSDPS310.A11
CSDPS310GS13: CSDPS310.D14
CSDPS310GS14: CSDPS310.A13
CSDPS310GS15: CSDPS310.D16
CSDPS310GS16: CSDPS310.A15
CSDPS310P1: CSDPS310.B1
CSDPS310P2: CSDPS310.C2
CSDPS310P3: CSDPS310.B3
CSDPS310P4: CSDPS310.C4
CSDPS310P5: CSDPS310.B5
CSDPS310P6: CSDPS310.C6
CSDPS310P7: CSDPS310.B7
CSDPS310P8: CSDPS310.C8
CSDPS310P9: CSDPS310.B9
CSDPS310P10: CSDPS310.C10
CSDPS310P11: CSDPS310.B11
CSDPS310P12: CSDPS310.C12
CSDPS310P13: CSDPS310.B13
CSDPS310P14: CSDPS310.C14
CSDPS310P15: CSDPS310.B15
CSDPS310P16: CSDPS310.C16
CSDPS310PS1: CSDPS310.D1
CSDPS310PS2: CSDPS310.A2
CSDPS310PS3: CSDPS310.D3
CSDPS310PS4: CSDPS310.A4
CSDPS310PS5: CSDPS310.D5
CSDPS310PS6: CSDPS310.A6
CSDPS310PS7: CSDPS310.D7
CSDPS310PS8: CSDPS310.A8
CSDPS310PS9: CSDPS310.D9
CSDPS310PS10: CSDPS310.A10
CSDPS310PS11: CSDPS310.D11
CSDPS310PS12: CSDPS310.A12
CSDPS310PS13: CSDPS310.D13
CSDPS310PS14: CSDPS310.A14
CSDPS310PS15: CSDPS310.D15
CSDPS310PS16: CSDPS310.A16
CSDPS314GS1: CSDPS314.D2
CSDPS314GS2: CSDPS314.A1
CSDPS314GS3: CSDPS314.D4
CSDPS314GS4: CSDPS314.A3
CSDPS314GS5: CSDPS314.D6
CSDPS314GS6: CSDPS314.A5
CSDPS314GS7: CSDPS314.D8
CSDPS314GS8: CSDPS314.A7
CSDPS314GS9: CSDPS314.D10
CSDPS314GS10: CSDPS314.A9
CSDPS314GS11: CSDPS314.D12
CSDPS314GS12: CSDPS314.A11
CSDPS314GS13: CSDPS314.D14
CSDPS314GS14: CSDPS314.A13
CSDPS314GS15: CSDPS314.D16
CSDPS314GS16: CSDPS314.A15
CSDPS314P1: CSDPS314.B1
CSDPS314P2: CSDPS314.C2
CSDPS314P3: CSDPS314.B3
CSDPS314P4: CSDPS314.C4
CSDPS314P5: CSDPS314.B5
CSDPS314P6: CSDPS314.C6
CSDPS314P7: CSDPS314.B7
CSDPS314P8: CSDPS314.C8
CSDPS314P9: CSDPS314.B9
CSDPS314P10: CSDPS314.C10
CSDPS314P11: CSDPS314.B11
CSDPS314P12: CSDPS314.C12
CSDPS314P13: CSDPS314.B13
CSDPS314P14: CSDPS314.C14
CSDPS314P15: CSDPS314.B15
CSDPS314P16: CSDPS314.C16
CSDPS314PS1: CSDPS314.D1
CSDPS314PS2: CSDPS314.A2
CSDPS314PS3: CSDPS314.D3
CSDPS314PS4: CSDPS314.A4
CSDPS314PS5: CSDPS314.D5
CSDPS314PS6: CSDPS314.A6
CSDPS314PS7: CSDPS314.D7
CSDPS314PS8: CSDPS314.A8
CSDPS314PS9: CSDPS314.D9
CSDPS314PS10: CSDPS314.A10
CSDPS314PS11: CSDPS314.D11
CSDPS314PS12: CSDPS314.A12
CSDPS314PS13: CSDPS314.D13
CSDPS314PS14: CSDPS314.A14
CSDPS314PS15: CSDPS314.D15
CSDPS314PS16: CSDPS314.A16
CSDPS319GS1: CSDPS319.D2
CSDPS319GS2: CSDPS319.A1
CSDPS319GS3: CSDPS319.D4
CSDPS319GS4: CSDPS319.A3
CSDPS319GS5: CSDPS319.D6
CSDPS319GS6: CSDPS319.A5
CSDPS319GS7: CSDPS319.D8
CSDPS319GS8: CSDPS319.A7
CSDPS319GS9: CSDPS319.D10
CSDPS319GS10: CSDPS319.A9
CSDPS319GS11: CSDPS319.D12
CSDPS319GS12: CSDPS319.A11
CSDPS319GS13: CSDPS319.D14
CSDPS319GS14: CSDPS319.A13
CSDPS319GS15: CSDPS319.D16
CSDPS319GS16: CSDPS319.A15
CSDPS319P1: CSDPS319.B1
CSDPS319P2: CSDPS319.C2
CSDPS319P3: CSDPS319.B3
CSDPS319P4: CSDPS319.C4
CSDPS319P5: CSDPS319.B5
CSDPS319P6: CSDPS319.C6
CSDPS319P7: CSDPS319.B7
CSDPS319P8: CSDPS319.C8
CSDPS319P9: CSDPS319.B9
CSDPS319P10: CSDPS319.C10
CSDPS319P11: CSDPS319.B11
CSDPS319P12: CSDPS319.C12
CSDPS319P13: CSDPS319.B13
CSDPS319P14: CSDPS319.C14
CSDPS319P15: CSDPS319.B15
CSDPS319P16: CSDPS319.C16
CSDPS319PS1: CSDPS319.D1
CSDPS319PS2: CSDPS319.A2
CSDPS319PS3: CSDPS319.D3
CSDPS319PS4: CSDPS319.A4
CSDPS319PS5: CSDPS319.D5
CSDPS319PS6: CSDPS319.A6
CSDPS319PS7: CSDPS319.D7
CSDPS319PS8: CSDPS319.A8
CSDPS319PS9: CSDPS319.D9
CSDPS319PS10: CSDPS319.A10
CSDPS319PS11: CSDPS319.D11
CSDPS319PS12: CSDPS319.A12
CSDPS319PS13: CSDPS319.D13
CSDPS319PS14: CSDPS319.A14
CSDPS319PS15: CSDPS319.D15
CSDPS319PS16: CSDPS319.A16
CSDPS323GS1: CSDPS323.D2
CSDPS323GS2: CSDPS323.A1
CSDPS323GS3: CSDPS323.D4
CSDPS323GS4: CSDPS323.A3
CSDPS323GS5: CSDPS323.D6
CSDPS323GS6: CSDPS323.A5
CSDPS323GS7: CSDPS323.D8
CSDPS323GS8: CSDPS323.A7
CSDPS323GS9: CSDPS323.D10
CSDPS323GS10: CSDPS323.A9
CSDPS323GS11: CSDPS323.D12
CSDPS323GS12: CSDPS323.A11
CSDPS323GS13: CSDPS323.D14
CSDPS323GS14: CSDPS323.A13
CSDPS323GS15: CSDPS323.D16
CSDPS323GS16: CSDPS323.A15
CSDPS323P1: CSDPS323.B1
CSDPS323P2: CSDPS323.C2
CSDPS323P3: CSDPS323.B3
CSDPS323P4: CSDPS323.C4
CSDPS323P5: CSDPS323.B5
CSDPS323P6: CSDPS323.C6
CSDPS323P7: CSDPS323.B7
CSDPS323P8: CSDPS323.C8
CSDPS323P9: CSDPS323.B9
CSDPS323P10: CSDPS323.C10
CSDPS323P11: CSDPS323.B11
CSDPS323P12: CSDPS323.C12
CSDPS323P13: CSDPS323.B13
CSDPS323P14: CSDPS323.C14
CSDPS323P15: CSDPS323.B15
CSDPS323P16: CSDPS323.C16
CSDPS323PS1: CSDPS323.D1
CSDPS323PS2: CSDPS323.A2
CSDPS323PS3: CSDPS323.D3
CSDPS323PS4: CSDPS323.A4
CSDPS323PS5: CSDPS323.D5
CSDPS323PS6: CSDPS323.A6
CSDPS323PS7: CSDPS323.D7
CSDPS323PS8: CSDPS323.A8
CSDPS323PS9: CSDPS323.D9
CSDPS323PS10: CSDPS323.A10
CSDPS323PS11: CSDPS323.D11
CSDPS323PS12: CSDPS323.A12
CSDPS323PS13: CSDPS323.D13
CSDPS323PS14: CSDPS323.A14
CSDPS323PS15: CSDPS323.D15
CSDPS323PS16: CSDPS323.A16
CSDPS426GS1: CSDPS426.D2
CSDPS426GS2: CSDPS426.A1
CSDPS426GS3: CSDPS426.D4
CSDPS426GS4: CSDPS426.A3
CSDPS426GS5: CSDPS426.D6
CSDPS426GS6: CSDPS426.A5
CSDPS426GS7: CSDPS426.D8
CSDPS426GS8: CSDPS426.A7
CSDPS426GS9: CSDPS426.D10
CSDPS426GS10: CSDPS426.A9
CSDPS426GS11: CSDPS426.D12
CSDPS426GS12: CSDPS426.A11
CSDPS426GS13: CSDPS426.D14
CSDPS426GS14: CSDPS426.A13
CSDPS426GS15: CSDPS426.D16
CSDPS426GS16: CSDPS426.A15
CSDPS426P1: CSDPS426.B1
CSDPS426P2: CSDPS426.C2
CSDPS426P3: CSDPS426.B3
CSDPS426P4: CSDPS426.C4
CSDPS426P5: CSDPS426.B5
CSDPS426P6: CSDPS426.C6
CSDPS426P7: CSDPS426.B7
CSDPS426P8: CSDPS426.C8
CSDPS426P9: CSDPS426.B9
CSDPS426P10: CSDPS426.C10
CSDPS426P11: CSDPS426.B11
CSDPS426P12: CSDPS426.C12
CSDPS426P13: CSDPS426.B13
CSDPS426P14: CSDPS426.C14
CSDPS426P15: CSDPS426.B15
CSDPS426P16: CSDPS426.C16
CSDPS426PS1: CSDPS426.D1
CSDPS426PS2: CSDPS426.A2
CSDPS426PS3: CSDPS426.D3
CSDPS426PS4: CSDPS426.A4
CSDPS426PS5: CSDPS426.D5
CSDPS426PS6: CSDPS426.A6
CSDPS426PS7: CSDPS426.D7
CSDPS426PS8: CSDPS426.A8
CSDPS426PS9: CSDPS426.D9
CSDPS426PS10: CSDPS426.A10
CSDPS426PS11: CSDPS426.D11
CSDPS426PS12: CSDPS426.A12
CSDPS426PS13: CSDPS426.D13
CSDPS426PS14: CSDPS426.A14
CSDPS426PS15: CSDPS426.D15
CSDPS426PS16: CSDPS426.A16
CSDPS426WW: CSDPS426.B17
CSDPS426XX: CSDPS426.C17
CSDPS430GS1: CSDPS430.D2
CSDPS430GS2: CSDPS430.A1
CSDPS430GS3: CSDPS430.D4
CSDPS430GS4: CSDPS430.A3
CSDPS430GS5: CSDPS430.D6
CSDPS430GS6: CSDPS430.A5
CSDPS430GS7: CSDPS430.D8
CSDPS430GS8: CSDPS430.A7
CSDPS430GS9: CSDPS430.D10
CSDPS430GS10: CSDPS430.A9
CSDPS430GS11: CSDPS430.D12
CSDPS430GS12: CSDPS430.A11
CSDPS430GS13: CSDPS430.D14
CSDPS430GS14: CSDPS430.A13
CSDPS430GS15: CSDPS430.D16
CSDPS430GS16: CSDPS430.A15
CSDPS430P1: CSDPS430.B1
CSDPS430P2: CSDPS430.C2
CSDPS430P3: CSDPS430.B3
CSDPS430P4: CSDPS430.C4
CSDPS430P5: CSDPS430.B5
CSDPS430P6: CSDPS430.C6
CSDPS430P7: CSDPS430.B7
CSDPS430P8: CSDPS430.C8
CSDPS430P9: CSDPS430.B9
CSDPS430P10: CSDPS430.C10
CSDPS430P11: CSDPS430.B11
CSDPS430P12: CSDPS430.C12
CSDPS430P13: CSDPS430.B13
CSDPS430P14: CSDPS430.C14
CSDPS430P15: CSDPS430.B15
CSDPS430P16: CSDPS430.C16
CSDPS430PS1: CSDPS430.D1
CSDPS430PS2: CSDPS430.A2
CSDPS430PS3: CSDPS430.D3
CSDPS430PS4: CSDPS430.A4
CSDPS430PS5: CSDPS430.D5
CSDPS430PS6: CSDPS430.A6
CSDPS430PS7: CSDPS430.D7
CSDPS430PS8: CSDPS430.A8
CSDPS430PS9: CSDPS430.D9
CSDPS430PS10: CSDPS430.A10
CSDPS430PS11: CSDPS430.D11
CSDPS430PS12: CSDPS430.A12
CSDPS430PS13: CSDPS430.D13
CSDPS430PS14: CSDPS430.A14
CSDPS430PS15: CSDPS430.D15
CSDPS430PS16: CSDPS430.A16
CSDPS430WW: CSDPS430.B17
CSDPS430XX: CSDPS430.C17
D231_MCB1_CT2: D231.17
D231_MCB1_E+: D231.16
D231_MCB1_E-: D231.15
D231_MCB1_EE+: D231.08
D231_MCB1_EE-: D231.07
D231_MCB1_F+: D231.14
D231_MCB1_F-: D231.13
D231_MCB1_FF+: D231.06
D231_MCB1_FF-: D231.05
D231_MCB1_G+: D231.12
D231_MCB1_G-: D231.11
D231_MCB1_GG+: D231.04
D231_MCB1_GG-: D231.03
D231_MCB1_H+: D231.10
D231_MCB1_H-: D231.09
D231_MCB1_HH+: D231.02
D231_MCB1_HH-: D231.01
D232_MCB1_CT2: D232.17
D232_MCB1_E+: D232.16
D232_MCB1_E-: D232.15
D232_MCB1_EE+: D232.08
D232_MCB1_EE-: D232.07
D232_MCB1_F+: D232.14
D232_MCB1_F-: D232.13
D232_MCB1_FF+: D232.06
D232_MCB1_FF-: D232.05
D232_MCB1_G+: D232.12
D232_MCB1_G-: D232.11
D232_MCB1_GG+: D232.04
D232_MCB1_GG-: D232.03
D232_MCB1_H+: D232.10
D232_MCB1_H-: D232.09
D232_MCB1_HH+: D232.02
D232_MCB1_HH-: D232.01
D431_MCB1_A+: D431.16
D431_MCB1_A-: D431.15
D431_MCB1_AA+: D431.08
D431_MCB1_AA-: D431.07
D431_MCB1_B+: D431.14
D431_MCB1_B-: D431.13
D431_MCB1_BB+: D431.06
D431_MCB1_BB-: D431.05
D431_MCB1_C+: D431.12
D431_MCB1_C-: D431.11
D431_MCB1_CC+: D431.04
D431_MCB1_CC-: D431.03
D431_MCB1_CT1: D431.17 D432.17
D431_MCB1_D+: D431.10
D431_MCB1_D-: D431.09
D431_MCB1_DD+: D431.02
D431_MCB1_DD-: D431.01
D432_MCB1_A+: D432.16
D432_MCB1_A-: D432.15
D432_MCB1_AA+: D432.08
D432_MCB1_AA-: D432.07
D432_MCB1_B+: D432.14
D432_MCB1_B-: D432.13
D432_MCB1_BB+: D432.06
D432_MCB1_BB-: D432.05
D432_MCB1_C+: D432.12
D432_MCB1_C-: D432.11
D432_MCB1_CC+: D432.04
D432_MCB1_CC-: D432.03
D432_MCB1_D+: D432.10
D432_MCB1_D-: D432.09
D432_MCB1_DD+: D432.02
D432_MCB1_DD-: D432.01
D10101: D101.01
D10102: D101.02
D10103: D101.03
D10104: D101.04
D10105: D101.05
D10106: D101.06
D10107: D101.07
D10108: D101.08
D10109: D101.09
D10110: D101.10
D10111: D101.11
D10112: D101.12
D10113: D101.13
D10114: D101.14
D10115: D101.15
D10116: D101.16
D10201: D102.01
D10202: D102.02
D10203: D102.03
D10204: D102.04
D10205: D102.05
D10206: D102.06
D10207: D102.07
D10208: D102.08
D10209: D102.09
D10210: D102.10
D10211: D102.11
D10212: D102.12
D10213: D102.13
D10214: D102.14
D10215: D102.15
D10216: D102.16
D10301: D103.01
D10302: D103.02
D10303: D103.03
D10304: D103.04
D10305: D103.05
D10306: D103.06
D10307: D103.07
D10308: D103.08
D10309: D103.09
D10310: D103.10
D10311: D103.11
D10312: D103.12
D10313: D103.13
D10314: D103.14
D10315: D103.15
D10316: D103.16
D10401: D104.01
D10402: D104.02
D10403: D104.03
D10404: D104.04
D10405: D104.05
D10406: D104.06
D10407: D104.07
D10408: D104.08
D10409: D104.09
D10410: D104.10
D10411: D104.11
D10412: D104.12
D10413: D104.13
D10414: D104.14
D10415: D104.15
D10416: D104.16
D10501: D105.01
D10502: D105.02
D10503: D105.03
D10504: D105.04
D10505: D105.05
D10506: D105.06
D10507: D105.07
D10508: D105.08
D10509: D105.09
D10510: D105.10
D10511: D105.11
D10512: D105.12
D10513: D105.13
D10514: D105.14
D10515: D105.15
D10516: D105.16
D10601: D106.01
D10602: D106.02
D10603: D106.03
D10604: D106.04
D10605: D106.05
D10606: D106.06
D10607: D106.07
D10608: D106.08
D10609: D106.09
D10610: D106.10
D10611: D106.11
D10612: D106.12
D10613: D106.13
D10614: D106.14
D10615: D106.15
D10616: D106.16
D10701: D107.01
D10702: D107.02
D10703: D107.03
D10704: D107.04
D10705: D107.05
D10706: D107.06
D10707: D107.07
D10708: D107.08
D10709: D107.09
D10710: D107.10
D10711: D107.11
D10712: D107.12
D10713: D107.13
D10714: D107.14
D10715: D107.15
D10716: D107.16
D10801: D108.01
D10802: D108.02
D10803: D108.03
D10804: D108.04
D10805: D108.05
D10806: D108.06
D10807: D108.07
D10808: D108.08
D10809: D108.09
D10810: D108.10
D10811: D108.11
D10812: D108.12
D10813: D108.13
D10814: D108.14
D10815: D108.15
D10816: D108.16
D10901: D109.01
D10902: D109.02
D10903: D109.03
D10904: D109.04
D10905: D109.05
D10906: D109.06
D10907: D109.07
D10908: D109.08
D10909: D109.09
D10910: D109.10
D10911: D109.11
D10912: D109.12
D10913: D109.13
D10914: D109.14
D10915: D109.15
D10916: D109.16
D11001: D110.01
D11002: D110.02
D11003: D110.03
D11004: D110.04
D11005: D110.05
D11006: D110.06
D11007: D110.07
D11008: D110.08
D11009: D110.09
D11010: D110.10
D11011: D110.11
D11012: D110.12
D11013: D110.13
D11014: D110.14
D11015: D110.15
D11016: D110.16
D11101: D111.01
D11102: D111.02
D11103: D111.03
D11104: D111.04
D11105: D111.05
D11106: D111.06
D11107: D111.07
D11108: D111.08
D11109: D111.09
D11110: D111.10
D11111: D111.11
D11112: D111.12
D11113: D111.13
D11114: D111.14
D11115: D111.15
D11116: D111.16
D11201: D112.01
D11202: D112.02
D11203: D112.03
D11204: D112.04
D11205: D112.05
D11206: D112.06
D11207: D112.07
D11208: D112.08
D11209: D112.09
D11210: D112.10
D11211: D112.11
D11212: D112.12
D11213: D112.13
D11214: D112.14
D11215: D112.15
D11216: D112.16
D11301: D113.01
D11302: D113.02
D11303: D113.03
D11304: D113.04
D11305: D113.05
D11306: D113.06
D11307: D113.07
D11308: D113.08
D11309: D113.09
D11310: D113.10
D11311: D113.11
D11312: D113.12
D11313: D113.13
D11314: D113.14
D11315: D113.15
D11316: D113.16
D11401: D114.01
D11402: D114.02
D11403: D114.03
D11404: D114.04
D11405: D114.05
D11406: D114.06
D11407: D114.07
D11408: D114.08
D11409: D114.09
D11410: D114.10
D11411: D114.11
D11412: D114.12
D11413: D114.13
D11414: D114.14
D11415: D114.15
D11416: D114.16
D11501: D115.01
D11502: D115.02
D11503: D115.03
D11504: D115.04
D11505: D115.05
D11506: D115.06
D11507: D115.07
D11508: D115.08
D11509: D115.09
D11510: D115.10
D11511: D115.11
D11512: D115.12
D11513: D115.13
D11514: D115.14
D11515: D115.15
D11516: D115.16
D11601: D116.01
D11602: D116.02
D11603: D116.03
D11604: D116.04
D11605: D116.05
D11606: D116.06
D11607: D116.07
D11608: D116.08
D11609: D116.09
D11610: D116.10
D11611: D116.11
D11612: D116.12
D11613: D116.13
D11614: D116.14
D11615: D116.15
D11616: D116.16
D11701: D117.01
D11702: D117.02
D11703: D117.03
D11704: D117.04
D11705: D117.05
D11706: D117.06
D11707: D117.07
D11708: D117.08
D11709: D117.09
D11710: D117.10
D11711: D117.11
D11712: D117.12
D11713: D117.13
D11714: D117.14
D11715: D117.15
D11716: D117.16
D11801: D118.01
D11802: D118.02
D11803: D118.03
D11804: D118.04
D11805: D118.05
D11806: D118.06
D11807: D118.07
D11808: D118.08
D11809: D118.09
D11810: D118.10
D11811: D118.11
D11812: D118.12
D11813: D118.13
D11814: D118.14
D11815: D118.15
D11816: D118.16
D11901: D119.01
D11902: D119.02
D11903: D119.03
D11904: D119.04
D11905: D119.05
D11906: D119.06
D11907: D119.07
D11908: D119.08
D11909: D119.09
D11910: D119.10
D11911: D119.11
D11912: D119.12
D11913: D119.13
D11914: D119.14
D11915: D119.15
D11916: D119.16
D12001: D120.01
D12002: D120.02
D12003: D120.03
D12004: D120.04
D12005: D120.05
D12006: D120.06
D12007: D120.07
D12008: D120.08
D12009: D120.09
D12010: D120.10
D12011: D120.11
D12012: D120.12
D12013: D120.13
D12014: D120.14
D12015: D120.15
D12016: D120.16
D12101: D121.01
D12102: D121.02
D12103: D121.03
D12104: D121.04
D12105: D121.05
D12106: D121.06
D12107: D121.07
D12108: D121.08
D12109: D121.09
D12110: D121.10
D12111: D121.11
D12112: D121.12
D12113: D121.13
D12114: D121.14
D12115: D121.15
D12116: D121.16
D12201: D122.01
D12202: D122.02
D12203: D122.03
D12204: D122.04
D12205: D122.05
D12206: D122.06
D12207: D122.07
D12208: D122.08
D12209: D122.09
D12210: D122.10
D12211: D122.11
D12212: D122.12
D12213: D122.13
D12214: D122.14
D12215: D122.15
D12216: D122.16
D12301: D123.01
D12302: D123.02
D12303: D123.03
D12304: D123.04
D12305: D123.05
D12306: D123.06
D12307: D123.07
D12308: D123.08
D12309: D123.09
D12310: D123.10
D12311: D123.11
D12312: D123.12
D12313: D123.13
D12314: D123.14
D12315: D123.15
D12316: D123.16
D12401: D124.01
D12402: D124.02
D12403: D124.03
D12404: D124.04
D12405: D124.05
D12406: D124.06
D12407: D124.07
D12408: D124.08
D12409: D124.09
D12410: D124.10
D12411: D124.11
D12412: D124.12
D12413: D124.13
D12414: D124.14
D12415: D124.15
D12416: D124.16
MSDPS1_1F: DPS1.C03
MSDPS1_1GRD: DPS1.B02
MSDPS1_1GS: DPS1.A02
MSDPS1_1S: DPS1.C02
MSDPS1_2F: DPS1.C07
MSDPS1_2GRD: DPS1.B06
MSDPS1_2GS: DPS1.A06
MSDPS1_2S: DPS1.C06
MSDPS1_3F: DPS1.C13
MSDPS1_3GRD: DPS1.B12
MSDPS1_3GS: DPS1.A12
MSDPS1_3S: DPS1.C12
MSDPS1_4F: DPS1.C17
MSDPS1_4GRD: DPS1.B16
MSDPS1_4GS: DPS1.A16
MSDPS1_4S: DPS1.C16
MSDPS1_5F: DPS1.A03
MSDPS1_5GS: DPS1.B01
MSDPS1_5S: DPS1.B03
MSDPS1_6F: DPS1.A07
MSDPS1_6GS: DPS1.B05
MSDPS1_6S: DPS1.B07
MSDPS1_7F: DPS1.A13
MSDPS1_7GS: DPS1.B11
MSDPS1_7S: DPS1.B13
MSDPS1_8F: DPS1.A17
MSDPS1_8GS: DPS1.B15
MSDPS1_8S: DPS1.B17
MSDPS1_TR+: DPS1.A09
MSDPS1_VB+: DPS1.C09
MSDPS2_1F: DPS2.C03
MSDPS2_1GRD: DPS2.B02
MSDPS2_1GS: DPS2.A02
MSDPS2_1S: DPS2.C02
MSDPS2_2F: DPS2.C07
MSDPS2_2GRD: DPS2.B06
MSDPS2_2GS: DPS2.A06
MSDPS2_2S: DPS2.C06
MSDPS2_3F: DPS2.C13
MSDPS2_3GRD: DPS2.B12
MSDPS2_3GS: DPS2.A12
MSDPS2_3S: DPS2.C12
MSDPS2_4F: DPS2.C17
MSDPS2_4GRD: DPS2.B16
MSDPS2_4GS: DPS2.A16
MSDPS2_4S: DPS2.C16
MSDPS2_5F: DPS2.A03
MSDPS2_5GS: DPS2.B01
MSDPS2_5S: DPS2.B03
MSDPS2_6F: DPS2.A07
MSDPS2_6GS: DPS2.B05
MSDPS2_6S: DPS2.B07
MSDPS2_7F: DPS2.A13
MSDPS2_7GS: DPS2.B11
MSDPS2_7S: DPS2.B13
MSDPS2_8F: DPS2.A17
MSDPS2_8GS: DPS2.B15
MSDPS2_8S: DPS2.B17
MSDPS2_TR+: DPS2.A09
MSDPS2_VB+: DPS2.C09
MSDPS3_1F: DPS3.C03
MSDPS3_1GRD: DPS3.B02
MSDPS3_1GS: DPS3.A02
MSDPS3_1S: DPS3.C02
MSDPS3_2F: DPS3.C07
MSDPS3_2GRD: DPS3.B06
MSDPS3_2GS: DPS3.A06
MSDPS3_2S: DPS3.C06
MSDPS3_3F: DPS3.C13
MSDPS3_3GRD: DPS3.B12
MSDPS3_3GS: DPS3.A12
MSDPS3_3S: DPS3.C12
MSDPS3_4F: DPS3.C17
MSDPS3_4GRD: DPS3.B16
MSDPS3_4GS: DPS3.A16
MSDPS3_4S: DPS3.C16
MSDPS3_5F: DPS3.A03
MSDPS3_5GS: DPS3.B01
MSDPS3_5S: DPS3.B03
MSDPS3_6F: DPS3.A07
MSDPS3_6GS: DPS3.B05
MSDPS3_6S: DPS3.B07
MSDPS3_7F: DPS3.A13
MSDPS3_7GS: DPS3.B11
MSDPS3_7S: DPS3.B13
MSDPS3_8F: DPS3.A17
MSDPS3_8GS: DPS3.B15
MSDPS3_8S: DPS3.B17
MSDPS3_TR+: DPS3.A09
MSDPS3_VB+: DPS3.C09
MSDPS8_1F: DPS8.C03
MSDPS8_1GRD: DPS8.B02
MSDPS8_1GS: DPS8.A02
MSDPS8_1S: DPS8.C02
MSDPS8_2F: DPS8.C07
MSDPS8_2GRD: DPS8.B06
MSDPS8_2GS: DPS8.A06
MSDPS8_2S: DPS8.C06
MSDPS8_3F: DPS8.C13
MSDPS8_3GRD: DPS8.B12
MSDPS8_3GS: DPS8.A12
MSDPS8_3S: DPS8.C12
MSDPS8_4F: DPS8.C17
MSDPS8_4GRD: DPS8.B16
MSDPS8_4GS: DPS8.A16
MSDPS8_4S: DPS8.C16
MSDPS8_5F: DPS8.A03
MSDPS8_5GS: DPS8.B01
MSDPS8_5S: DPS8.B03
MSDPS8_6F: DPS8.A07
MSDPS8_6GS: DPS8.B05
MSDPS8_6S: DPS8.B07
MSDPS8_7F: DPS8.A13
MSDPS8_7GS: DPS8.B11
MSDPS8_7S: DPS8.B13
MSDPS8_8F: DPS8.A17
MSDPS8_8GS: DPS8.B15
MSDPS8_8S: DPS8.B17
MSDPS8_TR+: DPS8.A09
MSDPS8_VB+: DPS8.C09
UDBGND: CB1.2 CB2.2 CB3.2 CB4.2 CB5.2 CB6.2 CB7.2 CB8.2 UTL1.A02 UTL1.A08 UTL1.A10 UTL1.A12 UTL1.A14 UTL1.B01 UTL1.B07 UTL1.B09 UTL1.B11 UTL1.B13 UTL2.A02 UTL2.A08 UTL2.A10 UTL2.A12 UTL2.A14 UTL2.B01 UTL2.B07 UTL2.B09 UTL2.B11 UTL2.B13 UTL3.A02 UTL3.A08 UTL3.A10 UTL3.A12 UTL3.A14 UTL3.B01 UTL3.B07 UTL3.B09 UTL3.B11 UTL3.B13 UTL4.A02 UTL4.A08 UTL4.A10 UTL4.A12 UTL4.A14 UTL4.B01 UTL4.B07 UTL4.B09 UTL4.B11 UTL4.B13 ; also on sheet 20 25 26 27 28
UT1_PDCF: UTL1.B15
UT1_PDCS: UTL1.A15
UT1_PGDS: UTL1.A16
UT1_PGRD: UTL1.B16
UT1_UP5V: CB1.1 CB2.1 CB3.1 CB4.1 CB5.1 CB6.1 CB7.1 CB8.1 UTL1.A05 UTL1.B04 UTL2.A05 UTL2.B04 UTL3.A05 UTL3.B04 UTL4.A05 UTL4.B04 ; also on sheet 2 4 6 8 10 12 14 17 19 20 25 26 27 28 30 31 32 33 34 35 36 37
UT1_URW00: UT1_SW1.8 UTL1.A01
UT1_URW01: UT1_SW1.7 UTL1.B02
UT1_URW02: UT1_SW1.6 UTL1.A03
UT1_URW03: UT1_SW1.5 UTL1.B03
UT1_URW04: UT1_SW1.4 UTL1.A04
UT1_URW05: UT1_SW1.3 UTL1.B05
UT1_URW06: UT1_SW1.2 UTL1.A06
UT1_UW07: UT1_SW1.1 UTL1.B06
UT1_UW08: UT1_SW2.8 UTL1.A07
UT1_UW09: UT1_SW2.7 UTL1.B08
UT1_UW10: UT1_SW2.6 UTL1.A09
UT1_UW11: UT1_SW2.5 UTL1.B10
UT1_UW12: UT1_SW2.4 UTL1.A11
UT1_UW13: UT1_SW2.3 UTL1.B12
UT1_UW14: UT1_SW2.2 UTL1.A13 ; also on sheet 20
UT1_UW15: UT1_SW2.1 UTL1.B14 ; also on sheet 20
UT2_PDCF: UTL2.B15
UT2_PDCS: UTL2.A15
UT2_PGDS: UTL2.A16
UT2_PGRD: UTL2.B16
UT2_URW00: UT2_SW1.8 UTL2.A01
UT2_URW01: UT2_SW1.7 UTL2.B02
UT2_URW02: UT2_SW1.6 UTL2.A03
UT2_URW03: UT2_SW1.5 UTL2.B03
UT2_URW04: UT2_SW1.4 UTL2.A04
UT2_URW05: UT2_SW1.3 UTL2.B05
UT2_URW06: UT2_SW1.2 UTL2.A06
UT2_UW07: UT2_SW1.1 UTL2.B06
UT2_UW08: UT2_SW2.8 UTL2.A07
UT2_UW09: UT2_SW2.7 UTL2.B08
UT2_UW10: UT2_SW2.6 UTL2.A09
UT2_UW11: UT2_SW2.5 UTL2.B10
UT2_UW12: UT2_SW2.4 UTL2.A11
UT2_UW13: UT2_SW2.3 UTL2.B12
UT2_UW14: UT2_SW2.2 UTL2.A13
UT2_UW15: UT2_SW2.1 UTL2.B14
UT3_PDCF: UTL3.B15
UT3_PDCS: UTL3.A15
UT3_PGDS: UTL3.A16
UT3_PGRD: UTL3.B16
UT3_URW00: UT3_SW1.8 UTL3.A01
UT3_URW01: UT3_SW1.7 UTL3.B02
UT3_URW02: UT3_SW1.6 UTL3.A03
UT3_URW03: UT3_SW1.5 UTL3.B03
UT3_URW04: UT3_SW1.4 UTL3.A04
UT3_URW05: UT3_SW1.3 UTL3.B05
UT3_URW06: UT3_SW1.2 UTL3.A06
UT3_UW07: UT3_SW1.1 UTL3.B06
UT3_UW08: UT3_SW2.8 UTL3.A07
UT3_UW09: UT3_SW2.7 UTL3.B08
UT3_UW10: UT3_SW2.6 UTL3.A09
UT3_UW11: UT3_SW2.5 UTL3.B10
UT3_UW12: UT3_SW2.4 UTL3.A11
UT3_UW13: UT3_SW2.3 UTL3.B12
UT3_UW14: UT3_SW2.2 UTL3.A13
UT3_UW15: UT3_SW2.1 UTL3.B14
UT4_PDCF: UTL4.B15
UT4_PDCS: UTL4.A15
UT4_PGDS: UTL4.A16
UT4_PGRD: UTL4.B16
UT4_URW00: UT4_SW1.8 UTL4.A01
UT4_URW01: UT4_SW1.7 UTL4.B02
UT4_URW02: UT4_SW1.6 UTL4.A03
UT4_URW03: UT4_SW1.5 UTL4.B03
UT4_URW04: UT4_SW1.4 UTL4.A04
UT4_URW05: UT4_SW1.3 UTL4.B05
UT4_URW06: UT4_SW1.2 UTL4.A06
UT4_UW07: UT4_SW1.1 UTL4.B06
UT4_UW08: UT4_SW2.8 UTL4.A07
UT4_UW09: UT4_SW2.7 UTL4.B08
UT4_UW10: UT4_SW2.6 UTL4.A09
UT4_UW11: UT4_SW2.5 UTL4.B10
UT4_UW12: UT4_SW2.4 UTL4.A11
UT4_UW13: UT4_SW2.3 UTL4.B12
UT4_UW14: UT4_SW2.2 UTL4.A13
UT4_UW15: UT4_SW2.1 UTL4.B14

Not connected (* = marked no-connect by the designer): CSDPS303 A17* B17* C17* D17*; CSDPS307 A17* B17* C17* D17*; CSDPS310 A17* B17* C17* D17*; CSDPS314 A17* B17* C17* D17*; CSDPS319 A17* B17* C17* D17*; CSDPS323 A17* B17* C17* D17*; CSDPS426 A17* D17*; CSDPS430 A17* D17*; D101 17* A17* B17*; D102 17* A17* B17*; D103 17* A17* B17*; D104 17* A17* B17*; D105 17* A17* B17*; D106 17* A17* B17*; D107 17* A17* B17*; D108 17* A17* B17*; D109 17* A17* B17*; D110 17* A17* B17*; D111 17* A17* B17*; D112 17* A17* B17*; D113 17* A17* B17*; D114 17* A17* B17*; D115 17* A17* B17*; D116 17* A17* B17*; D117 17* A17* B17*; D118 17* A17* B17*; D119 17* A17* B17*; D120 17* A17* B17*; D121 17* A17* B17*; D122 17* A17* B17*; D123 17* A17* B17*; D124 17* A17* B17*; D225 01* 02* 03* 04* 05* 06* 07* 08* 09* 10* 11* 12* 13* 14* 15* 16* 17* A1* A2* A3* A4* A5* A6* A7* A8* A9* A10* A11* A12* A13* A14* A15* A16* A17* B1* B2* B3* B4* B5* B6* B7* B8* B9* B10* B11* B12* B13* B14* B15* B16* B17*; D226/D626 A1* A2* A3* A4* A5* A6* A7* A8* A9* A10* A11* A12* A13* A14* A15* A16* A17* B1* B2* B3* B4* B5* B6* B7* B8* B9* B10* B11* B12* B13* B14* B15* B16* B17* C1* C2* C3* C4* C5* C6* C7* C8* C9* C10* C11* C12* C13* C14* C15* C16* C17* D2* D3* D4* D5* D6* D7* D8* D9* D10* D11* D12* D13* D14* D15* D16*; D227 01* 02* 03* 04* 05* 06* 07* 08* 09* 10* 11* 12* 13* 14* 15* 16* 17*; D228 01* 02* 03* 04* 05* 06* 07* 08* 09* 10* 11* 12* 13* 14* 15* 16* 17*; D229 01* 02* 03* 04* 05* 06* 07* 08* 09* 10* 11* 12* 13* 14* 15* 16* 17* A1* A2* A3* A4* A5* A6* A7* A8* A9* A10* A11* A12* A13* A14* A15* A16* A17* B1* B2* B3* B4* B5* B6* B7* B8* B9* B10* B11* B12* B13* B14* B15* B16* B17*; D230/D630 A1* A2* A3* A4* A5* A6* A7* A8* A9* A10* A11* A12* A13* A14* A15* A16* A17* B1* B2* B3* B4* B5* B6* B7* B8* B9* B10* B11* B12* B13* B14* B15* B16* B17* C1* C2* C3* C4* C5* C6* C7* C8* C9* C10* C11* C12* C13* C14* C15* C16* C17* D2* D3* D4* D5* D6* D7* D8* D9* D10* D11* D12* D13* D14* D15* D16*; D425 01* 02* 03* 04* 05* 06* 07* 08* 09* 10* 11* 12* 13* 14* 15* 16* 17* A1* A2* A3* A4* A5* A6* A7* A8* A9* A10* A11* A12* A13* A14* A15* A16* A17* B1* B2* B3* B4* B5* B6* B7* B8* B9* B10* B11* B12* B13* B14* B15* B16* B17*; D427 01* 02* 03* 04* 05* 06* 07* 08* 09* 10* 11* 12* 13* 14* 15* 16* 17*; D428 01* 02* 03* 04* 05* 06* 07* 08* 09* 10* 11* 12* 13* 14* 15* 16* 17*; D429 01* 02* 03* 04* 05* 06* 07* 08* 09* 10* 11* 12* 13* 14* 15* 16* 17* A1* A2* A3* A4* A5* A6* A7* A8* A9* A10* A11* A12* A13* A14* A15* A16* A17* B1* B2* B3* B4* B5* B6* B7* B8* B9* B10* B11* B12* B13* B14* B15* B16* B17*; DPS1 A04* A08* A10* A14* B04* B08* B10* B14* C04* C08* C10* C14*; DPS2 A04* A08* A10* A14* B04* B08* B10* B14* C04* C08* C10* C14*; DPS3 A04* A08* A10* A14* B04* B08* B10* B14* C04* C08* C10* C14*; DPS8 A04* A08* A10* A14* B04* B08* B10* B14* C04* C08* C10* C14*; UTL1 A17* B17*; UTL2 A17* B17*; UTL3 A17* B17*; UTL4 A17* B17*

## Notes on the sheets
sheet 21
- GROUP1
- DPS64
- D105
- D305
- D106
- D306
- D107
- D307
- D108
- D308
- DPS64
- D101
- D301
- D102
- D302
- D103
- D303
- D104
- D304
sheet 22
- GROUP2
- D113
- D313
- D114
- D314
- D115
- D315
- D116
- D316
- D109
- D309
- D110
- D310
- D111
- D311
- D112
- D312
- V93000 GROUP1
- VY22520
- V93000 GROUP1
- VY22520
sheet 23
- GROUP3
- DPS64
- PS RF FE1
- D121
- D321
- D122
- D322
- D123
- D323
- D124
- D324
- PS RF SRC-3-4
- DPS64
- D117
- D317
- D118
- D318
- D119
- D319
- D120
- D320
- EEPROM
- V93000 GROUP1
- VY22520
sheet 24
- GROUP8
- DPS64_1
- DPS64_1
- PS RF FE1
- PS RF FE2
- MCB S/M1
- MCB S/M1
- MCB S/M2
- MCB S/M2
- D229
- D429
- D230
- D430
- D231
- D431
- D232
- D432
- Half Size : WGD is in slot 430
- D231:¬°CAPTURE
- D431:¬°SOURCE+CAPTURE
- E.F.G.H¸û±`¨Ï¥Î
- A.B.C.D¸û±`¨Ï¥Î
- 3/4 Size  : WGD is in slot 230
- EE.FF.GG.HH¬°MCB(MBAV8)¤~¦³
- AA.BB.CC.DD¬°MCB(MBAV8)¤~¦³
- PS RF SRC-1-2
- DPS32
- DPS32
- MCC
- MCC
- PS RF SRC-3-4
- MCB M/M
- MCB M/M
- D225
- D425
- D226
- D426
- D227
- D427
- D228
- D428
- V93000 GROUP1
- VY22520
